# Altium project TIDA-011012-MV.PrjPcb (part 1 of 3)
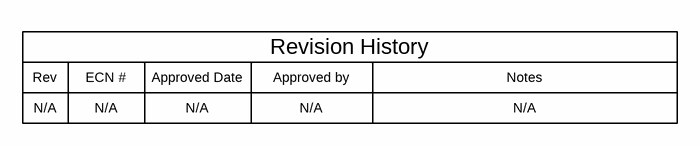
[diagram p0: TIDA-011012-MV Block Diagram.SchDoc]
CopyrightYear: 2026; EVM_orderable: NA; PCB_Rev: E1; PRJ_Customer: Public Release; PRJ_Engineer: A. Lechner/ R. Ruffo; PRJ_Number: TIDA-011012-MV; PRJ_Title: Change in menu Project|Project Options|Parameters; SCH_Rev: E1; TechSupport: http://www.ti.com/support; TID: TIDA-011012-MV
11 sheets, 567 parts. Net scope: hierarchical (ports join the sheet entries above them; power ports are global).
Board file: TIDA-011012-MV.PcbDoc
Sheets:
  TIDA-011012-MV Block Diagram.SchDoc
  TIDA-011012-MV Power Conversion.SchDoc
    U_TIDA-011012 Fans and Temp Sense = TIDA-011012-MV Fans and Temp Sense.SchDoc
    U_TIDA-011012 Optical Interface = TIDA-011012-MV Optical Interface.SchDoc
    U_TIDA-011012 Communication = TIDA-011012-MV Communication.SchDoc
    U_TIDA-011012 AC IV Sensing = TIDA-011012-MV AC IV Sensing.SchDoc
    U_TIDA-011012 DC IV Sensing = TIDA-011012-MV DC IV Sensing.SchDoc
    U_TIDA-011012 Current Comparator = TIDA-011012-MV Current Comparator.SchDoc
    U_TIDA-011012 Switch Node Hall Current Sensing = TIDA-011012-MV Switch Node Hall Current Sensing.SchDoc
    U_TIDA-011012 Auxiliary Power = TIDA-011012-MV Auxiliary Power.SchDoc
    U_TIDA-011012_Hardware = TIDA-011012-MV_Hardware.SchDoc

## Sheet TIDA-011012-MV Block Diagram.SchDoc
size 431 x 279 mm; Date: Not shown in title block; ApprovedBy: Not shown in title block; CheckedBy: Not shown in title block; Author: Not shown in title block; CompanyName: Not shown in title block; Engineer: Not shown in title block; Organization: Not shown in title block; Address1: Not shown in title block; Address2: Not shown in title block; Address3: Not shown in title block; Address4: Not shown in title block; DocumentNumber: 1; Revision: Use project parameter SCH_Rev; SheetNumber: 1; SheetTotal: 11; PageSetup: Record=PageOptions¦CenterHorizontal=True¦CenterVertical=True¦PrintScale=1.00¦XCorrection=1.00¦YCorrection=1.00¦PrintKind=0¦BorderSize=5000000¦LeftOffset=0¦BottomOffset=0¦Orientation=2¦PaperLength=1000¦PaperWidth=1000¦Scale=100¦PaperSource=15¦PrintQuality=600¦MediaType=1¦DitherType=10¦PaperKind=Letter¦PrintScaleMode=1

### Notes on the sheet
- Rev
- N/A
- ECN #
- Approved Date
- Approved by
- Revision History
- Notes

## Sheet TIDA-011012-MV Power Conversion.SchDoc
size 431 x 279 mm; Date: Not shown in title block; ApprovedBy: Not shown in title block; CheckedBy: Not shown in title block; Author: Not shown in title block; CompanyName: Not shown in title block; Engineer: Not shown in title block; Organization: Not shown in title block; Address1: Not shown in title block; Address2: Not shown in title block; Address3: Not shown in title block; Address4: Not shown in title block; DocumentNumber: 2; Revision: Use project parameter SCH_Rev; SheetNumber: 2; SheetTotal: 11; PageSetup: Record=PageOptions¦CenterHorizontal=True¦CenterVertical=True¦PrintScale=1.00¦XCorrection=1.00¦YCorrection=1.00¦PrintKind=0¦BorderSize=5000000¦LeftOffset=0¦BottomOffset=0¦Orientation=2¦PaperLength=1000¦PaperWidth=1000¦Scale=100¦PaperSource=15¦PrintQuality=600¦MediaType=1¦DitherType=10¦PaperKind=Letter¦PrintScaleMode=1
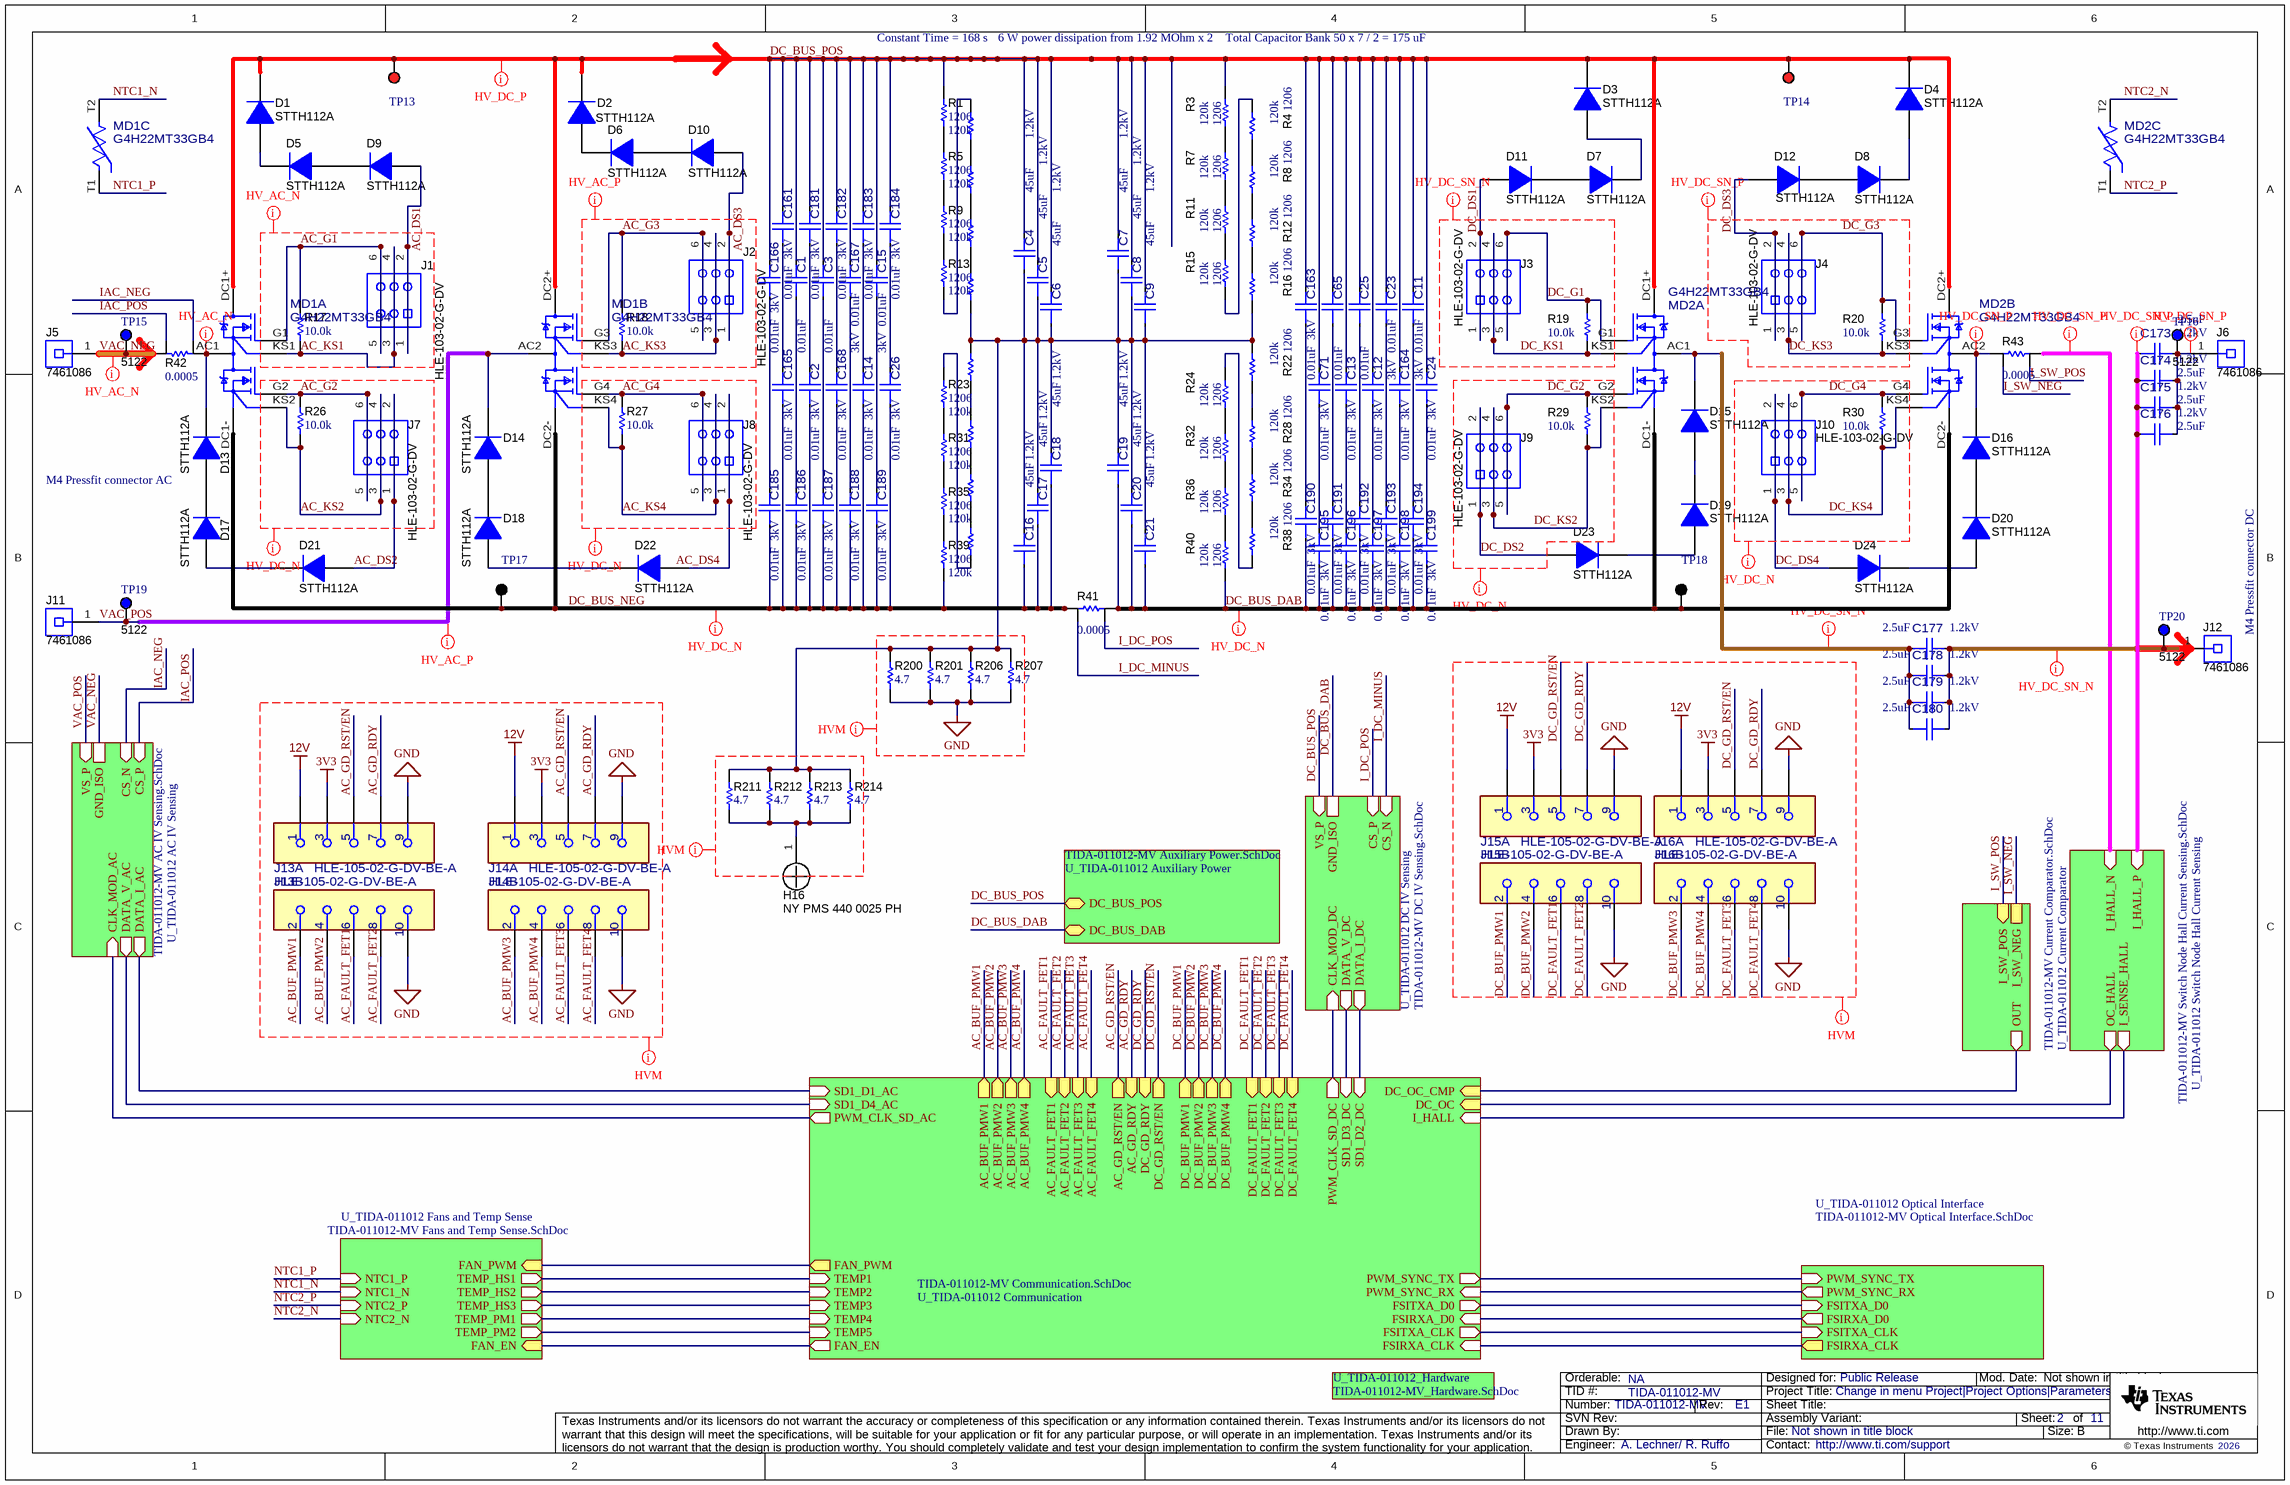
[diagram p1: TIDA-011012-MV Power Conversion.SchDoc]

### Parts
C1  ValueDisplayed: 0.01uF  [FP-C2220X103KHRAC7800_2220-MFG]  (hidden comment: C2220X103KHRAC7800)
C2  ValueDisplayed: 0.01uF  VDC_V: 3kV  [FP-C2220X103KHRAC7800_2220-MFG]  (hidden comment: C2220X103KHRAC7800)
C3  ValueDisplayed: 0.01uF  [FP-C2220X103KHRAC7800_2220-MFG]  (hidden comment: C2220X103KHRAC7800)
C4  ValueDisplayed: 45uF  VDC_V: 1.2kV  [FP-C4AQPEW5450M3BJ_RADIAL-MFG]  (hidden comment: C4AQPEW5450M3BJ)
C5  ValueDisplayed: 45uF  VDC_V: 1.2kV  [FP-C4AQPEW5450M3BJ_RADIAL-MFG]  (hidden comment: C4AQPEW5450M3BJ)
C6  ValueDisplayed: 45uF  VDC_V: 1.2kV  [FP-C4AQPEW5450M3BJ_RADIAL-MFG]  (hidden comment: C4AQPEW5450M3BJ)
C7  ValueDisplayed: 45uF  VDC_V: 1.2kV  [FP-C4AQPEW5450M3BJ_RADIAL-MFG]  (hidden comment: C4AQPEW5450M3BJ)
C8  ValueDisplayed: 45uF  VDC_V: 1.2kV  [FP-C4AQPEW5450M3BJ_RADIAL-MFG]  (hidden comment: C4AQPEW5450M3BJ)
C9  ValueDisplayed: 45uF  VDC_V: 1.2kV  [FP-C4AQPEW5450M3BJ_RADIAL-MFG]  (hidden comment: C4AQPEW5450M3BJ)
C11  ValueDisplayed: 0.01uF  VDC_V: 3kV  [FP-C2220X103KHRAC7800_2220-MFG]  (hidden comment: C2220X103KHRAC7800)
C12  ValueDisplayed: 0.01uF  VDC_V: 3kV  [FP-C2220X103KHRAC7800_2220-MFG]  (hidden comment: C2220X103KHRAC7800)
C13  ValueDisplayed: 0.01uF  VDC_V: 3kV  [FP-C2220X103KHRAC7800_2220-MFG]  (hidden comment: C2220X103KHRAC7800)
C14  ValueDisplayed: 0.01uF  VDC_V: 3kV  [FP-C2220X103KHRAC7800_2220-MFG]  (hidden comment: C2220X103KHRAC7800)
C15  ValueDisplayed: 0.01uF  VDC_V: 3kV  [FP-C2220X103KHRAC7800_2220-MFG]  (hidden comment: C2220X103KHRAC7800)
C16  ValueDisplayed: 45uF  VDC_V: 1.2kV  [FP-C4AQPEW5450M3BJ_RADIAL-MFG]  (hidden comment: C4AQPEW5450M3BJ)
C17  ValueDisplayed: 45uF  VDC_V: 1.2kV  [FP-C4AQPEW5450M3BJ_RADIAL-MFG]  (hidden comment: C4AQPEW5450M3BJ)
C18  ValueDisplayed: 45uF  VDC_V: 1.2kV  [FP-C4AQPEW5450M3BJ_RADIAL-MFG]  (hidden comment: C4AQPEW5450M3BJ)
C19  ValueDisplayed: 45uF  VDC_V: 1.2kV  [FP-C4AQPEW5450M3BJ_RADIAL-MFG]  (hidden comment: C4AQPEW5450M3BJ)
C20  ValueDisplayed: 45uF  VDC_V: 1.2kV  [FP-C4AQPEW5450M3BJ_RADIAL-MFG]  (hidden comment: C4AQPEW5450M3BJ)
C21  ValueDisplayed: 45uF  VDC_V: 1.2kV  [FP-C4AQPEW5450M3BJ_RADIAL-MFG]  (hidden comment: C4AQPEW5450M3BJ)
C23  ValueDisplayed: 0.01uF  VDC_V: 3kV  [FP-C2220X103KHRAC7800_2220-MFG]  (hidden comment: C2220X103KHRAC7800)
C24  ValueDisplayed: 0.01uF  VDC_V: 3kV  [FP-C2220X103KHRAC7800_2220-MFG]  (hidden comment: C2220X103KHRAC7800)
C25  ValueDisplayed: 0.01uF  [FP-C2220X103KHRAC7800_2220-MFG]  (hidden comment: C2220X103KHRAC7800)
C26  ValueDisplayed: 0.01uF  VDC_V: 3kV  [FP-C2220X103KHRAC7800_2220-MFG]  (hidden comment: C2220X103KHRAC7800)
C65  ValueDisplayed: 0.01uF  [FP-C2220X103KHRAC7800_2220-MFG]  (hidden comment: C2220X103KHRAC7800)
C71  ValueDisplayed: 0.01uF  VDC_V: 3kV  [FP-C2220X103KHRAC7800_2220-MFG]  (hidden comment: C2220X103KHRAC7800)
C161  ValueDisplayed: 0.01uF  VDC_V: 3kV  [FP-C2220X103KHRAC7800_2220-MFG]  (hidden comment: C2220X103KHRAC7800)
C163  ValueDisplayed: 0.01uF  VDC_V: 3kV  [FP-C2220X103KHRAC7800_2220-MFG]  (hidden comment: C2220X103KHRAC7800)
C164  ValueDisplayed: 0.01uF  VDC_V: 3kV  [FP-C2220X103KHRAC7800_2220-MFG]  (hidden comment: C2220X103KHRAC7800)
C165  ValueDisplayed: 0.01uF  VDC_V: 3kV  [FP-C2220X103KHRAC7800_2220-MFG]  (hidden comment: C2220X103KHRAC7800)
C166  ValueDisplayed: 0.01uF  VDC_V: 3kV  [FP-C2220X103KHRAC7800_2220-MFG]  (hidden comment: C2220X103KHRAC7800)
C167  ValueDisplayed: 0.01uF  VDC_V: 3kV  [FP-C2220X103KHRAC7800_2220-MFG]  (hidden comment: C2220X103KHRAC7800)
C168  ValueDisplayed: 0.01uF  VDC_V: 3kV  [FP-C2220X103KHRAC7800_2220-MFG]  (hidden comment: C2220X103KHRAC7800)
C173  ValueDisplayed: 2.5uF  VDC_V: 1.2kV  [FP-C4ASPBW4250A3MJ_RADIAL-MFG]  (hidden comment: C4ASPBW4250A3MJ)
C174  ValueDisplayed: 2.5uF  VDC_V: 1.2kV  [FP-C4ASPBW4250A3MJ_RADIAL-MFG]  (hidden comment: C4ASPBW4250A3MJ)
C175  ValueDisplayed: 2.5uF  VDC_V: 1.2kV  [FP-C4ASPBW4250A3MJ_RADIAL-MFG]  (hidden comment: C4ASPBW4250A3MJ)
C176  ValueDisplayed: 2.5uF  VDC_V: 1.2kV  [FP-C4ASPBW4250A3MJ_RADIAL-MFG]  (hidden comment: C4ASPBW4250A3MJ)
C177  ValueDisplayed: 2.5uF  VDC_V: 1.2kV  [FP-C4ASPBW4250A3MJ_RADIAL-MFG]  (hidden comment: C4ASPBW4250A3MJ)
C178  ValueDisplayed: 2.5uF  VDC_V: 1.2kV  [FP-C4ASPBW4250A3MJ_RADIAL-MFG]  (hidden comment: C4ASPBW4250A3MJ)
C179  ValueDisplayed: 2.5uF  VDC_V: 1.2kV  [FP-C4ASPBW4250A3MJ_RADIAL-MFG]  (hidden comment: C4ASPBW4250A3MJ)
C180  ValueDisplayed: 2.5uF  VDC_V: 1.2kV  [FP-C4ASPBW4250A3MJ_RADIAL-MFG]  (hidden comment: C4ASPBW4250A3MJ)
C181  ValueDisplayed: 0.01uF  VDC_V: 3kV  [FP-C2220X103KHRAC7800_2220-MFG]  (hidden comment: C2220X103KHRAC7800)
C182  ValueDisplayed: 0.01uF  VDC_V: 3kV  [FP-C2220X103KHRAC7800_2220-MFG]  (hidden comment: C2220X103KHRAC7800)
C183  ValueDisplayed: 0.01uF  VDC_V: 3kV  [FP-C2220X103KHRAC7800_2220-MFG]  (hidden comment: C2220X103KHRAC7800)
C184  ValueDisplayed: 0.01uF  VDC_V: 3kV  [FP-C2220X103KHRAC7800_2220-MFG]  (hidden comment: C2220X103KHRAC7800)
C185  ValueDisplayed: 0.01uF  VDC_V: 3kV  [FP-C2220X103KHRAC7800_2220-MFG]  (hidden comment: C2220X103KHRAC7800)
C186  ValueDisplayed: 0.01uF  VDC_V: 3kV  [FP-C2220X103KHRAC7800_2220-MFG]  (hidden comment: C2220X103KHRAC7800)
C187  ValueDisplayed: 0.01uF  VDC_V: 3kV  [FP-C2220X103KHRAC7800_2220-MFG]  (hidden comment: C2220X103KHRAC7800)
C188  ValueDisplayed: 0.01uF  VDC_V: 3kV  [FP-C2220X103KHRAC7800_2220-MFG]  (hidden comment: C2220X103KHRAC7800)
C189  ValueDisplayed: 0.01uF  VDC_V: 3kV  [FP-C2220X103KHRAC7800_2220-MFG]  (hidden comment: C2220X103KHRAC7800)
C190  ValueDisplayed: 0.01uF  VDC_V: 3kV  [FP-C2220X103KHRAC7800_2220-MFG]  (hidden comment: C2220X103KHRAC7800)
C191  ValueDisplayed: 0.01uF  VDC_V: 3kV  [FP-C2220X103KHRAC7800_2220-MFG]  (hidden comment: C2220X103KHRAC7800)
C192  ValueDisplayed: 0.01uF  VDC_V: 3kV  [FP-C2220X103KHRAC7800_2220-MFG]  (hidden comment: C2220X103KHRAC7800)
C193  ValueDisplayed: 0.01uF  VDC_V: 3kV  [FP-C2220X103KHRAC7800_2220-MFG]  (hidden comment: C2220X103KHRAC7800)
C194  ValueDisplayed: 0.01uF  VDC_V: 3kV  [FP-C2220X103KHRAC7800_2220-MFG]  (hidden comment: C2220X103KHRAC7800)
C195  ValueDisplayed: 0.01uF  VDC_V: 3kV  [FP-C2220X103KHRAC7800_2220-MFG]  (hidden comment: C2220X103KHRAC7800)
C196  ValueDisplayed: 0.01uF  VDC_V: 3kV  [FP-C2220X103KHRAC7800_2220-MFG]  (hidden comment: C2220X103KHRAC7800)
C197  ValueDisplayed: 0.01uF  VDC_V: 3kV  [FP-C2220X103KHRAC7800_2220-MFG]  (hidden comment: C2220X103KHRAC7800)
C198  ValueDisplayed: 0.01uF  VDC_V: 3kV  [FP-C2220X103KHRAC7800_2220-MFG]  (hidden comment: C2220X103KHRAC7800)
C199  ValueDisplayed: 0.01uF  VDC_V: 3kV  [FP-C2220X103KHRAC7800_2220-MFG]  (hidden comment: C2220X103KHRAC7800)
D1  STTH112A  [SMA]
D2  STTH112A  [SMA]
D3  STTH112A  [SMA]
D4  STTH112A  [SMA]
D5  STTH112A  [SMA]
D6  STTH112A  [SMA]
D7  STTH112A  [SMA]
D8  STTH112A  [SMA]
D9  STTH112A  [SMA]
D10  STTH112A  [SMA]
D11  STTH112A  [SMA]
D12  STTH112A  [SMA]
D13  STTH112A  [SMA]
D14  STTH112A  [SMA]
D15  STTH112A  [SMA]
D16  STTH112A  [SMA]
D17  STTH112A  [SMA]
D18  STTH112A  [SMA]
D19  STTH112A  [SMA]
D20  STTH112A  [SMA]
D21  STTH112A  [SMA]
D22  STTH112A  [SMA]
D23  STTH112A  [SMA]
D24  STTH112A  [SMA]
H16  NY PMS 440 0025 PH  [NY PMS 440 0025 PH]
J1  HLE-103-02-G-DV  [Samtec_HLE-103-02-x-DV]
J2  HLE-103-02-G-DV  [Samtec_HLE-103-02-x-DV]
J3  HLE-103-02-G-DV  [Samtec_HLE-103-02-x-DV]
J4  HLE-103-02-G-DV  [Samtec_HLE-103-02-x-DV]
J5  7461086  [Wurth_7461086]
J6  7461086  [Wurth_7461086]
J7  HLE-103-02-G-DV  [Samtec_HLE-103-02-x-DV]
J8  HLE-103-02-G-DV  [Samtec_HLE-103-02-x-DV]
J9  HLE-103-02-G-DV  [Samtec_HLE-103-02-x-DV]
J10  HLE-103-02-G-DV  [Samtec_HLE-103-02-x-DV]
J11  7461086  [Wurth_7461086]
J12  7461086  [Wurth_7461086]
J13  HLE-105-02-G-DV-BE-A  [FP-HLE-105-02-G-DV-BE-A_CONN_RCPT_10-MFG]  (parts A,B of 2)
J14  HLE-105-02-G-DV-BE-A  [FP-HLE-105-02-G-DV-BE-A_CONN_RCPT_10-MFG]  (parts A,B of 2)
J15  HLE-105-02-G-DV-BE-A  [FP-HLE-105-02-G-DV-BE-A_CONN_RCPT_10-MFG]  (parts A,B of 2)
J16  HLE-105-02-G-DV-BE-A  [FP-HLE-105-02-G-DV-BE-A_CONN_RCPT_10-MFG]  (parts A,B of 2)
MD1  G4H22MT33GB4  [FP-G4H22MT33GB4_SiCPAK-G+_MODIFIED-MFG]  (parts A,B,C of 3)
MD2  G4H22MT33GB4  [FP-G4H22MT33GB4_SiCPAK-G+_MODIFIED-MFG]  (parts A,B,C of 3)
R1  ValueDisplayed: 120k  [1206]  (hidden comment: RC1206FR-07120KL)
R2  RC1206FR-07120KL  [1206]  (value not drawn)
R3  ValueDisplayed: 120k  [1206]  (hidden comment: RC1206FR-07120KL)
R4  ValueDisplayed: 120k  [1206]  (hidden comment: RC1206FR-07120KL)
R5  ValueDisplayed: 120k  [1206]  (hidden comment: RC1206FR-07120KL)
R6  RC1206FR-07120KL  [1206]  (value not drawn)
R7  ValueDisplayed: 120k  [1206]  (hidden comment: RC1206FR-07120KL)
R8  ValueDisplayed: 120k  [1206]  (hidden comment: RC1206FR-07120KL)
R9  ValueDisplayed: 120k  [1206]  (hidden comment: RC1206FR-07120KL)
R10  RC1206FR-07120KL  [1206]  (value not drawn)
R11  ValueDisplayed: 120k  [1206]  (hidden comment: RC1206FR-07120KL)
R12  ValueDisplayed: 120k  [1206]  (hidden comment: RC1206FR-07120KL)
R13  ValueDisplayed: 120k  [1206]  (hidden comment: RC1206FR-07120KL)
R14  RC1206FR-07120KL  [1206]  (value not drawn)
R15  ValueDisplayed: 120k  [1206]  (hidden comment: RC1206FR-07120KL)
R16  ValueDisplayed: 120k  [1206]  (hidden comment: RC1206FR-07120KL)
R17  ValueDisplayed: 10.0k  [0603]  (hidden comment: ERJ-3EKF1002V)
R18  ValueDisplayed: 10.0k  [0603]  (hidden comment: ERJ-3EKF1002V)
R19  ValueDisplayed: 10.0k  [0603]  (hidden comment: ERJ-3EKF1002V)
R20  ValueDisplayed: 10.0k  [0603]  (hidden comment: ERJ-3EKF1002V)
R21  RC1206FR-07120KL  [1206]  (value not drawn)
R22  ValueDisplayed: 120k  [1206]  (hidden comment: RC1206FR-07120KL)
R23  ValueDisplayed: 120k  [1206]  (hidden comment: RC1206FR-07120KL)
R24  ValueDisplayed: 120k  [1206]  (hidden comment: RC1206FR-07120KL)
R25  RC1206FR-07120KL  [1206]  (value not drawn)
R26  ValueDisplayed: 10.0k  [0603]  (hidden comment: ERJ-3EKF1002V)
R27  ValueDisplayed: 10.0k  [0603]  (hidden comment: ERJ-3EKF1002V)
R28  ValueDisplayed: 120k  [1206]  (hidden comment: RC1206FR-07120KL)
R29  ValueDisplayed: 10.0k  [0603]  (hidden comment: ERJ-3EKF1002V)
R30  ValueDisplayed: 10.0k  [0603]  (hidden comment: ERJ-3EKF1002V)
R31  ValueDisplayed: 120k  [1206]  (hidden comment: RC1206FR-07120KL)
R32  ValueDisplayed: 120k  [1206]  (hidden comment: RC1206FR-07120KL)
R33  RC1206FR-07120KL  [1206]  (value not drawn)
R34  ValueDisplayed: 120k  [1206]  (hidden comment: RC1206FR-07120KL)
R35  ValueDisplayed: 120k  [1206]  (hidden comment: RC1206FR-07120KL)
R36  ValueDisplayed: 120k  [1206]  (hidden comment: RC1206FR-07120KL)
R37  RC1206FR-07120KL  [1206]  (value not drawn)
R38  ValueDisplayed: 120k  [1206]  (hidden comment: RC1206FR-07120KL)
R39  ValueDisplayed: 120k  [1206]  (hidden comment: RC1206FR-07120KL)
R40  ValueDisplayed: 120k  [1206]  (hidden comment: RC1206FR-07120KL)
R41  ValueDisplayed: 0.0005  [WSL4026_0p5milli]  (hidden comment: WSL4026L5000FEB)
R42  ValueDisplayed: 0.0005  [WSL4026_0p5milli]  (hidden comment: WSL4026L5000FEB)
R43  ValueDisplayed: 0.0005  [WSL4026_0p5milli]  (hidden comment: WSL4026L5000FEB)
R200  ValueDisplayed: 4.7  [1206]  (hidden comment: CRCW12064R70JNEA)
R201  ValueDisplayed: 4.7  [1206]  (hidden comment: CRCW12064R70JNEA)
R206  ValueDisplayed: 4.7  [1206]  (hidden comment: CRCW12064R70JNEA)
R207  ValueDisplayed: 4.7  [1206]  (hidden comment: CRCW12064R70JNEA)
R211  ValueDisplayed: 4.7  [1206]  (hidden comment: CRCW12064R70JNEA)
R212  ValueDisplayed: 4.7  [1206]  (hidden comment: CRCW12064R70JNEA)
R213  ValueDisplayed: 4.7  [1206]  (hidden comment: CRCW12064R70JNEA)
R214  ValueDisplayed: 4.7  [1206]  (hidden comment: CRCW12064R70JNEA)
TP13  5010  [Keystone5010]  (value not drawn)
TP14  5010  [Keystone5010]  (value not drawn)
TP15  5122  [Keystone5122]
TP16  5122  [Keystone5122]
TP17  5011  [Keystone5011]  (value not drawn)
TP18  5011  [Keystone5011]  (value not drawn)
TP19  5122  [Keystone5122]
TP20  5122  [Keystone5122]

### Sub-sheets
U_TIDA-011012 AC IV Sensing = TIDA-011012-MV AC IV Sensing.SchDoc: CS_P (in), CS_N (in), DATA_I_AC (out), GND_ISO, VS_P (in), DATA_V_AC (out), CLK_MOD_AC (in)
U_TIDA-011012 Auxiliary Power = TIDA-011012-MV Auxiliary Power.SchDoc: DC_BUS_POS (bidir), DC_BUS_DAB (bidir)
U_TIDA-011012 Communication = TIDA-011012-MV Communication.SchDoc: SD1_D1_AC (in), SD1_D2_DC (in), SD1_D3_DC (in), SD1_D4_AC (in), PWM_CLK_SD_AC (out), FAN_EN (out), TEMP1 (in), TEMP2 (in), TEMP3 (in), TEMP4 (in), TEMP5 (in), FSITXA_D0 (out), PWM_SYNC_TX (out), PWM_SYNC_RX (in), I_HALL (in), PWM_CLK_SD_DC (out), AC_FAULT_FET1 (in), AC_FAULT_FET2 (in), AC_GD_RST/EN (out), AC_BUF_PMW1 (out), AC_BUF_PMW2 (out), AC_BUF_PMW3 (out), AC_BUF_PMW4 (out), DC_GD_RDY (in), DC_FAULT_FET1 (in), DC_OC (in), DC_OC_CMP (in), DC_BUF_PMW1 (out), DC_BUF_PMW2 (out), DC_BUF_PMW3 (out), DC_BUF_PMW4 (out), AC_FAULT_FET3 (in), AC_FAULT_FET4 (in), DC_FAULT_FET2 (in), DC_FAULT_FET3 (in), DC_FAULT_FET4 (in), DC_GD_RST/EN (out), AC_GD_RDY (in), FAN_PWM (out), FSIRXA_D0 (in), FSITXA_CLK (out), FSIRXA_CLK (in)
U_TIDA-011012 Current Comparator = TIDA-011012-MV Current Comparator.SchDoc: OUT (out), I_SW_NEG, I_SW_POS (in)
U_TIDA-011012 DC IV Sensing = TIDA-011012-MV DC IV Sensing.SchDoc: CS_P (in), CS_N (in), DATA_I_DC (out), GND_ISO, VS_P (in), DATA_V_DC (out), CLK_MOD_DC (in)
U_TIDA-011012 Fans and Temp Sense = TIDA-011012-MV Fans and Temp Sense.SchDoc: TEMP_HS1 (out), TEMP_HS2 (out), TEMP_HS3 (out), TEMP_PM2 (out), NTC1_P (in), NTC1_N (in), NTC2_P (in), NTC2_N (in), TEMP_PM1 (out), FAN_EN (in), FAN_PWM (in)
U_TIDA-011012 Optical Interface = TIDA-011012-MV Optical Interface.SchDoc: PWM_SYNC_RX (out), FSITXA_D0 (in), PWM_SYNC_TX (in), FSITXA_CLK (in), FSIRXA_D0 (out), FSIRXA_CLK (out)
U_TIDA-011012 Switch Node Hall Current Sensing = TIDA-011012-MV Switch Node Hall Current Sensing.SchDoc: I_HALL_P (in), I_HALL_N (in), I_SENSE_HALL (out), OC_HALL (out)
U_TIDA-011012_Hardware = TIDA-011012-MV_Hardware.SchDoc: no entries

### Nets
3V3: J13.3 J14.3 J15.3 J16.3
12V: J13.1 J14.1 J15.1 J16.1
GND: J13.9 J13.10 J14.9 J14.10 J15.9 J15.10 J16.9 J16.10 R200.1 R201.1 R206.1 R207.1
AC_BUF_PMW1: J13.2 ; sheet U_TIDA-011012 Communication/AC_BUF_PMW1
AC_BUF_PMW2: J13.4 ; sheet U_TIDA-011012 Communication/AC_BUF_PMW2
AC_BUF_PMW3: J14.2 ; sheet U_TIDA-011012 Communication/AC_BUF_PMW3
AC_BUF_PMW4: J14.4 ; sheet U_TIDA-011012 Communication/AC_BUF_PMW4
AC_DS1: D9.2(A) J1.1 J1.2
AC_DS2: D21.2(A) J7.1 J7.2
AC_DS3: D10.2(A) J2.1 J2.2
AC_FAULT_FET1: J13.6 ; sheet U_TIDA-011012 Communication/AC_FAULT_FET1
AC_FAULT_FET2: J13.8 ; sheet U_TIDA-011012 Communication/AC_FAULT_FET2
AC_FAULT_FET3: J14.6 ; sheet U_TIDA-011012 Communication/AC_FAULT_FET3
AC_FAULT_FET4: J14.8 ; sheet U_TIDA-011012 Communication/AC_FAULT_FET4
AC_G1: J1.5 J1.6 MD1.G1 R17.1
AC_G2: J7.5 J7.6 MD1.G2 R26.1
AC_G3: J2.5 J2.6 MD1.G3 R18.1
AC_G4: J8.5 J8.6 MD1.G4 R27.1
AC_GD_RDY: J13.7 J14.7 ; sheet U_TIDA-011012 Communication/AC_GD_RDY
AC_GD_RST/EN: J13.5 J14.5 ; sheet U_TIDA-011012 Communication/AC_GD_RST/EN
AC_KS1: J1.3 J1.4 MD1.KS1 R17.2
AC_KS2: J7.3 J7.4 MD1.KS2 R26.2
AC_KS3: J2.3 J2.4 MD1.KS3 R18.2
AC_KS4: J8.3 J8.4 MD1.KS4 R27.2
CLK_MOD_AC: sheet U_TIDA-011012 Communication/PWM_CLK_SD_AC, sheet U_TIDA-011012 AC IV Sensing/CLK_MOD_AC
CLK_MOD_DC: sheet U_TIDA-011012 Communication/PWM_CLK_SD_DC, sheet U_TIDA-011012 DC IV Sensing/CLK_MOD_DC
DATA_I_AC: sheet U_TIDA-011012 Communication/SD1_D1_AC, sheet U_TIDA-011012 AC IV Sensing/DATA_I_AC
DATA_I_DC: sheet U_TIDA-011012 Communication/SD1_D2_DC, sheet U_TIDA-011012 DC IV Sensing/DATA_I_DC
DATA_V_AC: sheet U_TIDA-011012 Communication/SD1_D4_AC, sheet U_TIDA-011012 AC IV Sensing/DATA_V_AC
DATA_V_DC: sheet U_TIDA-011012 Communication/SD1_D3_DC, sheet U_TIDA-011012 DC IV Sensing/DATA_V_DC
DC_BUF_PMW1: J15.2 ; sheet U_TIDA-011012 Communication/DC_BUF_PMW1
DC_BUF_PMW2: J15.4 ; sheet U_TIDA-011012 Communication/DC_BUF_PMW2
DC_BUF_PMW3: J16.2 ; sheet U_TIDA-011012 Communication/DC_BUF_PMW3
DC_BUF_PMW4: J16.4 ; sheet U_TIDA-011012 Communication/DC_BUF_PMW4
DC_BUS_DAB: C19.1 C20.1 C21.1 C190.1 C191.1 C192.1 C193.1 C194.1 C195.1 C196.1 C197.1 C198.1 C199.1 MD2.DC1- MD2.DC2- R40.1 R41.1 TP18.1 ; sheet U_TIDA-011012 DC IV Sensing/GND_ISO, sheet U_TIDA-011012 Auxiliary Power/DC_BUS_DAB
DC_BUS_NEG: C2.1 C14.1 C16.1 C17.1 C18.1 C26.1 C165.1 C168.1 C185.1 C186.1 C187.1 C188.1 C189.1 MD1.DC1- MD1.DC2- R39.1 R41.2 TP17.1
DC_BUS_POS: C1.2 C3.2 C4.2 C5.2 C6.2 C7.2 C8.2 C9.2 C11.2 C12.2 C13.2 C15.2 C23.2 C24.2 C25.2 C65.2 C71.2 C161.2 C163.2 C164.2 C166.2 C167.2 C181.2 C182.2 C183.2 C184.2 D1.1(K) D2.1(K) D3.1(K) D4.1(K) MD1.DC1+ MD1.DC2+ MD2.DC1+ MD2.DC2+ R1.2 R3.2 TP13.1 TP14.1 ; sheet U_TIDA-011012 DC IV Sensing/VS_P, sheet U_TIDA-011012 Auxiliary Power/DC_BUS_POS
DC_DS1: D11.2(A) J3.1 J3.2
DC_DS2: D23.2(A) J9.1 J9.2
DC_DS3: D12.2(A) J4.1 J4.2
DC_DS4: D24.2(A) J10.1 J10.2
DC_FAULT_FET1: J15.6 ; sheet U_TIDA-011012 Communication/DC_FAULT_FET1
DC_FAULT_FET2: J15.8 ; sheet U_TIDA-011012 Communication/DC_FAULT_FET2
DC_FAULT_FET3: J16.6 ; sheet U_TIDA-011012 Communication/DC_FAULT_FET3
DC_FAULT_FET4: J16.8 ; sheet U_TIDA-011012 Communication/DC_FAULT_FET4
DC_G1: J3.5 J3.6 MD2.G1 R19.2
DC_G2: J9.5 J9.6 MD2.G2 R29.2
DC_G3: J4.5 J4.6 MD2.G3 R20.2
DC_G4: J10.5 J10.6 MD2.G4 R30.2
DC_GD_RDY: J15.7 J16.7 ; sheet U_TIDA-011012 Communication/DC_GD_RDY
DC_GD_RST/EN: J15.5 J16.5 ; sheet U_TIDA-011012 Communication/DC_GD_RST/EN
DC_KS1: J3.3 J3.4 MD2.KS1 R19.1
DC_KS2: J9.3 J9.4 MD2.KS2 R29.1
DC_KS3: J4.3 J4.4 MD2.KS3 R20.1
DC_KS4: J10.3 J10.4 MD2.KS4 R30.1
DC_OC: sheet U_TIDA-011012 Communication/DC_OC, sheet U_TIDA-011012 Switch Node Hall Current Sensing/OC_HALL
DC_OC_CMP: sheet U_TIDA-011012 Communication/DC_OC_CMP, sheet U_TIDA-011012 Current Comparator/OUT
FAN_EN: sheet U_TIDA-011012 Fans and Temp Sense/FAN_EN, sheet U_TIDA-011012 Communication/FAN_EN
FAN_PWM: sheet U_TIDA-011012 Fans and Temp Sense/FAN_PWM, sheet U_TIDA-011012 Communication/FAN_PWM
FSIRXA_CLK: sheet U_TIDA-011012 Optical Interface/FSIRXA_CLK, sheet U_TIDA-011012 Communication/FSIRXA_CLK
FSIRXA_D0: sheet U_TIDA-011012 Optical Interface/FSIRXA_D0, sheet U_TIDA-011012 Communication/FSIRXA_D0
FSITXA_CLK: sheet U_TIDA-011012 Optical Interface/FSITXA_CLK, sheet U_TIDA-011012 Communication/FSITXA_CLK
FSITXA_D0: sheet U_TIDA-011012 Optical Interface/FSITXA_D0, sheet U_TIDA-011012 Communication/FSITXA_D0
I_DC_MINUS: R41.4 ; sheet U_TIDA-011012 DC IV Sensing/CS_N
I_DC_POS: R41.3 ; sheet U_TIDA-011012 DC IV Sensing/CS_P
I_HALL: sheet U_TIDA-011012 Communication/I_HALL, sheet U_TIDA-011012 Switch Node Hall Current Sensing/I_SENSE_HALL
I_HALL_N: R43.1 ; sheet U_TIDA-011012 Switch Node Hall Current Sensing/I_HALL_N
I_HALL_P: C173.1 C174.1 C175.1 C176.1 ; sheet U_TIDA-011012 Switch Node Hall Current Sensing/I_HALL_P
I_SW_NEG: R43.4 ; sheet U_TIDA-011012 Current Comparator/I_SW_NEG
I_SW_POS: R43.3 ; sheet U_TIDA-011012 Current Comparator/I_SW_POS
IAC_NEG: R42.3 ; sheet U_TIDA-011012 AC IV Sensing/CS_N
IAC_POS: R42.4 ; sheet U_TIDA-011012 AC IV Sensing/CS_P
NTC1_N: MD1.T2 ; sheet U_TIDA-011012 Fans and Temp Sense/NTC1_N
NTC1_P: MD1.T1 ; sheet U_TIDA-011012 Fans and Temp Sense/NTC1_P
NTC2_N: MD2.T2 ; sheet U_TIDA-011012 Fans and Temp Sense/NTC2_N
NTC2_P: MD2.T1 ; sheet U_TIDA-011012 Fans and Temp Sense/NTC2_P
PWM_SYNC_RX: sheet U_TIDA-011012 Optical Interface/PWM_SYNC_RX, sheet U_TIDA-011012 Communication/PWM_SYNC_RX
PWM_SYNC_TX: sheet U_TIDA-011012 Optical Interface/PWM_SYNC_TX, sheet U_TIDA-011012 Communication/PWM_SYNC_TX
TEMP1: sheet U_TIDA-011012 Fans and Temp Sense/TEMP_HS1, sheet U_TIDA-011012 Communication/TEMP1
TEMP2: sheet U_TIDA-011012 Fans and Temp Sense/TEMP_HS2, sheet U_TIDA-011012 Communication/TEMP2
TEMP3: sheet U_TIDA-011012 Fans and Temp Sense/TEMP_HS3, sheet U_TIDA-011012 Communication/TEMP3
TEMP4: sheet U_TIDA-011012 Fans and Temp Sense/TEMP_PM1, sheet U_TIDA-011012 Communication/TEMP4
TEMP5: sheet U_TIDA-011012 Fans and Temp Sense/TEMP_PM2, sheet U_TIDA-011012 Communication/TEMP5
VAC_NEG: J5.1 R42.2 TP15.1 ; sheet U_TIDA-011012 AC IV Sensing/GND_ISO  [project net GND_ISO_AC_SENS]
VAC_POS: D14.1(K) J11.1 MD1.AC2 TP19.1 ; sheet U_TIDA-011012 AC IV Sensing/VS_P
NetC1_1: C1.1 C186.2
NetC2_2: C2.2 C181.1
NetC3_1: C3.1 C187.2
NetC4_1: C4.1 C5.1 C6.1 C7.1 C8.1 C9.1 C16.2 C17.2 C18.2 C19.2 C20.2 C21.2 R14.2 R16.2 R21.1 R22.1 R200.2 R201.2 R206.2 R207.2 R211.2 R212.2 R213.2 R214.2
NetC11_1: C11.1 C194.2
NetC12_1: C12.1 C197.2
NetC13_1: C13.1 C196.2
NetC14_2: C14.2 C183.1
NetC15_1: C15.1 C189.2
NetC23_1: C23.1 C193.2
NetC24_1: C24.1 C199.2
NetC25_1: C25.1 C192.2
NetC26_2: C26.2 C184.1
NetC65_1: C65.1 C191.2
NetC71_1: C71.1 C195.2
NetC161_1: C161.1 C165.2
NetC163_1: C163.1 C190.2
NetC164_1: C164.1 C198.2
NetC166_1: C166.1 C185.2
NetC167_1: C167.1 C188.2
NetC168_2: C168.2 C182.1
NetC173_2: C173.2 C174.2 C175.2 C176.2 J6.1 TP16.1
NetC177_1: C177.1 C178.1 C179.1 C180.1 D15.1(K) MD2.AC1
NetC177_2: C177.2 C178.2 C179.2 C180.2 J12.1 TP20.1
NetD1_2: D1.2(A) D5.1(K)
NetD2_2: D2.2(A) D6.1(K)
NetD3_2: D3.2(A) D7.1(K)
NetD4_2: D4.2(A) D8.1(K)
NetD5_2: D5.2(A) D9.1(K)
NetD6_2: D6.2(A) D10.1(K)
NetD7_2: D7.2(A) D11.1(K)
NetD8_2: D8.2(A) D12.1(K)
NetD13_1: D13.1(K) MD1.AC1 R42.1
NetD13_2: D13.2(A) D17.1(K)
NetD14_2: D14.2(A) D18.1(K)
NetD15_2: D15.2(A) D19.1(K)
NetD16_1: D16.1(K) MD2.AC2 R43.2
NetD16_2: D16.2(A) D20.1(K)
NetD17_2: D17.2(A) D21.1(K)
NetD18_2: D18.2(A) D22.1(K)
NetD19_2: D19.2(A) D23.1(K)
NetD20_2: D20.2(A) D24.1(K)
NetD22_2: D22.2(A) J8.1 J8.2
NetH16_1: H16.1 R211.1 R212.1 R213.1 R214.1
NetR1_1: R1.1 R5.2
NetR2_1: R2.1 R13.1
NetR2_2: R2.2 R6.1
NetR3_1: R3.1 R7.2
NetR4_1: R4.1 R15.1
NetR4_2: R4.2 R8.1
NetR5_1: R5.1 R9.2
NetR6_2: R6.2 R10.1
NetR7_1: R7.1 R11.2
NetR8_2: R8.2 R12.1
NetR9_1: R9.1 R13.2
NetR10_2: R10.2 R14.1
NetR11_1: R11.1 R15.2
NetR12_2: R12.2 R16.1
NetR21_2: R21.2 R25.1
NetR22_2: R22.2 R28.1
NetR23_1: R23.1 R31.2
NetR23_2: R23.2 R37.2
NetR24_1: R24.1 R32.2
NetR24_2: R24.2 R38.2
NetR25_2: R25.2 R33.1
NetR28_2: R28.2 R34.1
NetR31_1: R31.1 R35.2
NetR32_1: R32.1 R36.2
NetR33_2: R33.2 R37.1
NetR34_2: R34.2 R38.1
NetR35_1: R35.1 R39.2
NetR36_1: R36.1 R40.2

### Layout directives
net class HV_AC_P: AC_G3, AC_KS3, VAC_POS
net class HV_AC_N: AC_G1, AC_KS1, GND_ISO_AC_SENS, NetD13_1
net class HV_DC_N: AC_G2, AC_G4, AC_KS2, AC_KS4, DC_BUS_DAB, DC_BUS_NEG, DC_DS2, DC_G2, DC_G4, DC_KS2, DC_KS4
net class HV_DC_P: DC_BUS_POS
net class HV_DC_SN_N: DC_DS1, DC_G1, DC_KS1, NetC177_1, NetC177_2
net class HV_DC_SN_P: DC_DS3, DC_G3, DC_KS3, I_HALL_N, I_HALL_P, NetC173_2, NetD16_1
net class HVM: 3V3, 12V, (no net found under the mark), AC_BUF_PMW1, AC_BUF_PMW2, AC_BUF_PMW3, AC_BUF_PMW4, AC_FAULT_FET1, AC_FAULT_FET2, AC_FAULT_FET3, AC_FAULT_FET4, AC_GD_RDY, AC_GD_RST/EN, DC_BUF_PMW1, DC_BUF_PMW2, DC_BUF_PMW3, DC_BUF_PMW4, DC_FAULT_FET1, DC_FAULT_FET2, DC_FAULT_FET3, DC_FAULT_FET4, DC_GD_RDY, DC_GD_RST/EN, GND

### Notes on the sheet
- Constant Time = 168 s
- 6 W power dissipation from 1.92 MOhm x 2
- Total Capacitor Bank 50 x 7 / 2 = 175 uF
- M4 Pressfit connector AC
- (near J12) M4 Pressfit connector DC
- Labels drawn without touching a wire or pin: AC_DS4

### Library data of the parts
C1-C3 C11-C15 C23-C26 C65 C71 C161 C163-C168 C181-C199 = CMP-0128868-1: 10000 pF ±10% 3000V (3kV) Ceramic Capacitor X7R 2220 (5750 Metric); Manufacturer: KEMET; AEC Grade: NA; AEC Qualified: No; Cap_F: 10nF; SizeZ_mm: 2.2mm; TempCo: 15%; Value: 10nF
C4-C9 C16-C21 = CMP-0128781-1: 45 µF Film Capacitor 1200V (1.2kV) Polypropylene (PP), Metallized Radial - 4 Leads; Manufacturer: KEMET; AEC Grade: Grade 2; AEC Qualified: Yes; Cap_F: 45µF; SizeZ_mm: 65.3mm; Tolerance_%: 5%; Value: 45µF
C173-C180 = CMP-0128874-1: 2.5 µF Film Capacitor 630V 1200V (1.2kV) Polypropylene (PP), Metallized Radial - 4 Leads; Manufacturer: KEMET; AEC Qualified: No; Cap_F: 2.5µF; SizeZ_mm: 45mm; Tolerance_%: 5%; Value: 2.5µF
D1-D24 = CMP-0077081-2: Diode, Ultrafast, 1200 V, 1 A, SMA; Manufacturer: STMicroelectronics; AEC Qualified: N; TJmax_C: 175°C; SizeX_mm: 5.59; Green_Lifecycle: Not Set; Io_A: 1A; Value2: 1.9V; SizeY_mm: 2.92; SizeZ_mm: 2.87; AEC Category: Q101; Value: 1200V; SizeAreaWB_mm2: 37.3428; Vr_V: 1.2kV; Green_REACh: Incomplete; SizeArea_mm2: 16.3228
H16 = CMP-0003617-1: Machine Screw, Round, #4-40 x 1/4, Nylon, Philips panhead; Manufacturer: B&F Fastener Supply; CompType: Hardware
J1-J4 J7-J10 = CMP-0082272-1: Receptacle, 2.54mm, 3x2, Gold, SMT; Manufacturer: Samtec; Pitch_mm: 2.54; Gender: Female; Cert_UL: Y; Voltage_V: 400V; Current_A: 4.1A; Row_Count: 2; CompType: Socket Strip
J5 J6 J11 J12 = CMP-0054757-1: Power Element Bush, M4, 12, TH; Manufacturer: Wurth Elektronik; CNHeader: FALSE; Gender: Female; CompType: Screw Terminal; Pitch_mm: 2.54
J13-J16 = CMP-0127514-1: Conn Socket Strip SKT 10 POS 2.54mm Solder ST Top Entry SMD Tube; Manufacturer: Samtec; ContactFinish: Gold,Nickel; Current_A: 4.1A; Row_Count: 2; Voltage_V: 566V; AEC Grade: NA; AEC Qualified: No; Conn Gender: Female; Conn Orientation: Vertical; Is Female: yes; SizeZ_mm: 3.79mm
MD1 MD2 = CMP-0128745-2: 3300V 22.5mΩ Full-Bridge / Dual-Half-Bridge SiC Module; Manufacturer: Navitas Semiconductor; AEC Qualified: No; IdsMax_A: 105A; QgTyp_nC: 590nC @ 18V; Rdson45_ohm: 22.5m; SizeZ_mm: 12.9mm; VdsMax_V: 3.3kV; Vgs_V: 18V; Input Capacitance At Vds: 13820pF @ 2000V; Threshold Vgs Max: 4.3V; Threshold Vgs Min: 2.5V; TJmax_C: +175°C; Typ Forward Diode Voltage: 4V; ChMode: Enhancement
R1 R3-R5 R7-R9 R11-R13 R15 R16 R22-R24 R28 R31 R32 R34-R36 R38-R40 = CMP-0017868-2: RES, 120 k, 1%, 0.25 W, 1206; Manufacturer: Yageo America; Power_W: 250mW; TempCo: 100 ppm/C; U/M: EA; Value: 120k; SizeX_mm: 3.2; SizeY_mm: 1.6; SizeZ_mm: 1.35; Value2: 0.25W; SizeArea_mm2: 5.12; VDC_V: 200V; AEC Category: Q200
R2 R6 R10 R14 R21 R25 R33 R37 = CMP-0017868-2: RES, 120 k, 1%, 0.25 W, 1206; Manufacturer: Yageo America; Power_W: 250mW; TempCo: 100 ppm/C; Value_Code: 120k; U/M: EA; Value: 120k; SizeX_mm: 3.2; SizeY_mm: 1.6; SizeZ_mm: 1.35; Value2: 0.25W; SizeArea_mm2: 5.12; VDC_V: 200V; AEC Category: Q200
R17-R20 R26 R27 R29 R30 = CMP-0022684-3: RES, 10.0 k, 1%, 0.1 W, 0603; Manufacturer: Panasonic; Power_W: 100mW; TempCo: 100 ppm/C; Value_Code: 10k0; U/M: EA; Value: 10.0k; EIA_Code: E96; Res_ohm: 10k; SizeX_mm: 1.6; SizeY_mm: 0.8; SizeZ_mm: 1; Value2: 0.1W; SizeArea_mm2: 1.28; VDC_V: 75V; AEC Category: Q200
R41-R43 = CMP-0065757-2: RES, 0.0005, 1%, 3 W, 4026; Manufacturer: Vishay-Dale; Power_W: 3W; TempCo: 75 ppm/C; Value_Code: L5000; U/M: EA; Value: 0.0005; Res_ohm: 500µ; CompType: Resistor; AEC Qualified: N; AEC Category: Q200
R200 R201 R206 R207 R211-R214 = CMP-0018693-3: RES, 4.7, 5%, 0.25 W, AEC-Q200 Grade 0, 1206; Manufacturer: Vishay-Dale; Power_W: 250mW; TempCo: 200 ppm/C; Value_Code: 4R70; Value: 4.7; EIA_Code: E24; SizeX_mm: 3.2; SizeY_mm: 1.6; SizeZ_mm: 1.35; Value2: 0.25W; SizeArea_mm2: 5.12; AEC Qualified: Y; VDC_V: 200V; AEC Category: Q200; AEC Grade: 0
TP13 TP14 = CMP-0055147-2: Test Point, Multipurpose, Red, TH; Manufacturer: Keystone Electronics; CT: TRUE; ContactFinish: Silver; Green_Lifecycle: Active; CNHeader: FALSE; Green_REACh: Passed
TP15 TP16 TP19 TP20 = CMP-0055155-2: Test Point, Compact, Blue, TH; Manufacturer: Keystone Electronics; Green_Lifecycle: Active; CNHeader: FALSE; ContactFinish: Silver; CT: TRUE; Green_REACh: Passed
TP17 TP18 = CMP-0055148-2: Test Point, Multipurpose, Black, TH; Manufacturer: Keystone Electronics; CNHeader: FALSE; ContactFinish: Silver; Green_REACh: Passed; Green_Lifecycle: Active; CT: TRUE

## Sheet TIDA-011012-MV Fans and Temp Sense.SchDoc
size 431 x 279 mm; Date: Not shown in title block; ApprovedBy: Not shown in title block; CheckedBy: Not shown in title block; Author: Not shown in title block; CompanyName: Not shown in title block; Engineer: Not shown in title block; Organization: Not shown in title block; Address1: Not shown in title block; Address2: Not shown in title block; Address3: Not shown in title block; Address4: Not shown in title block; DocumentNumber: 9; Revision: Use project parameter SCH_Rev; SheetNumber: 9; SheetTotal: 11; PageSetup: Record=PageOptions¦CenterHorizontal=True¦CenterVertical=True¦PrintScale=1.00¦XCorrection=1.00¦YCorrection=1.00¦PrintKind=0¦BorderSize=5000000¦LeftOffset=0¦BottomOffset=0¦Orientation=2¦PaperLength=1000¦PaperWidth=1000¦Scale=100¦PaperSource=15¦PrintQuality=600¦MediaType=1¦DitherType=10¦PaperKind=Letter¦PrintScaleMode=1
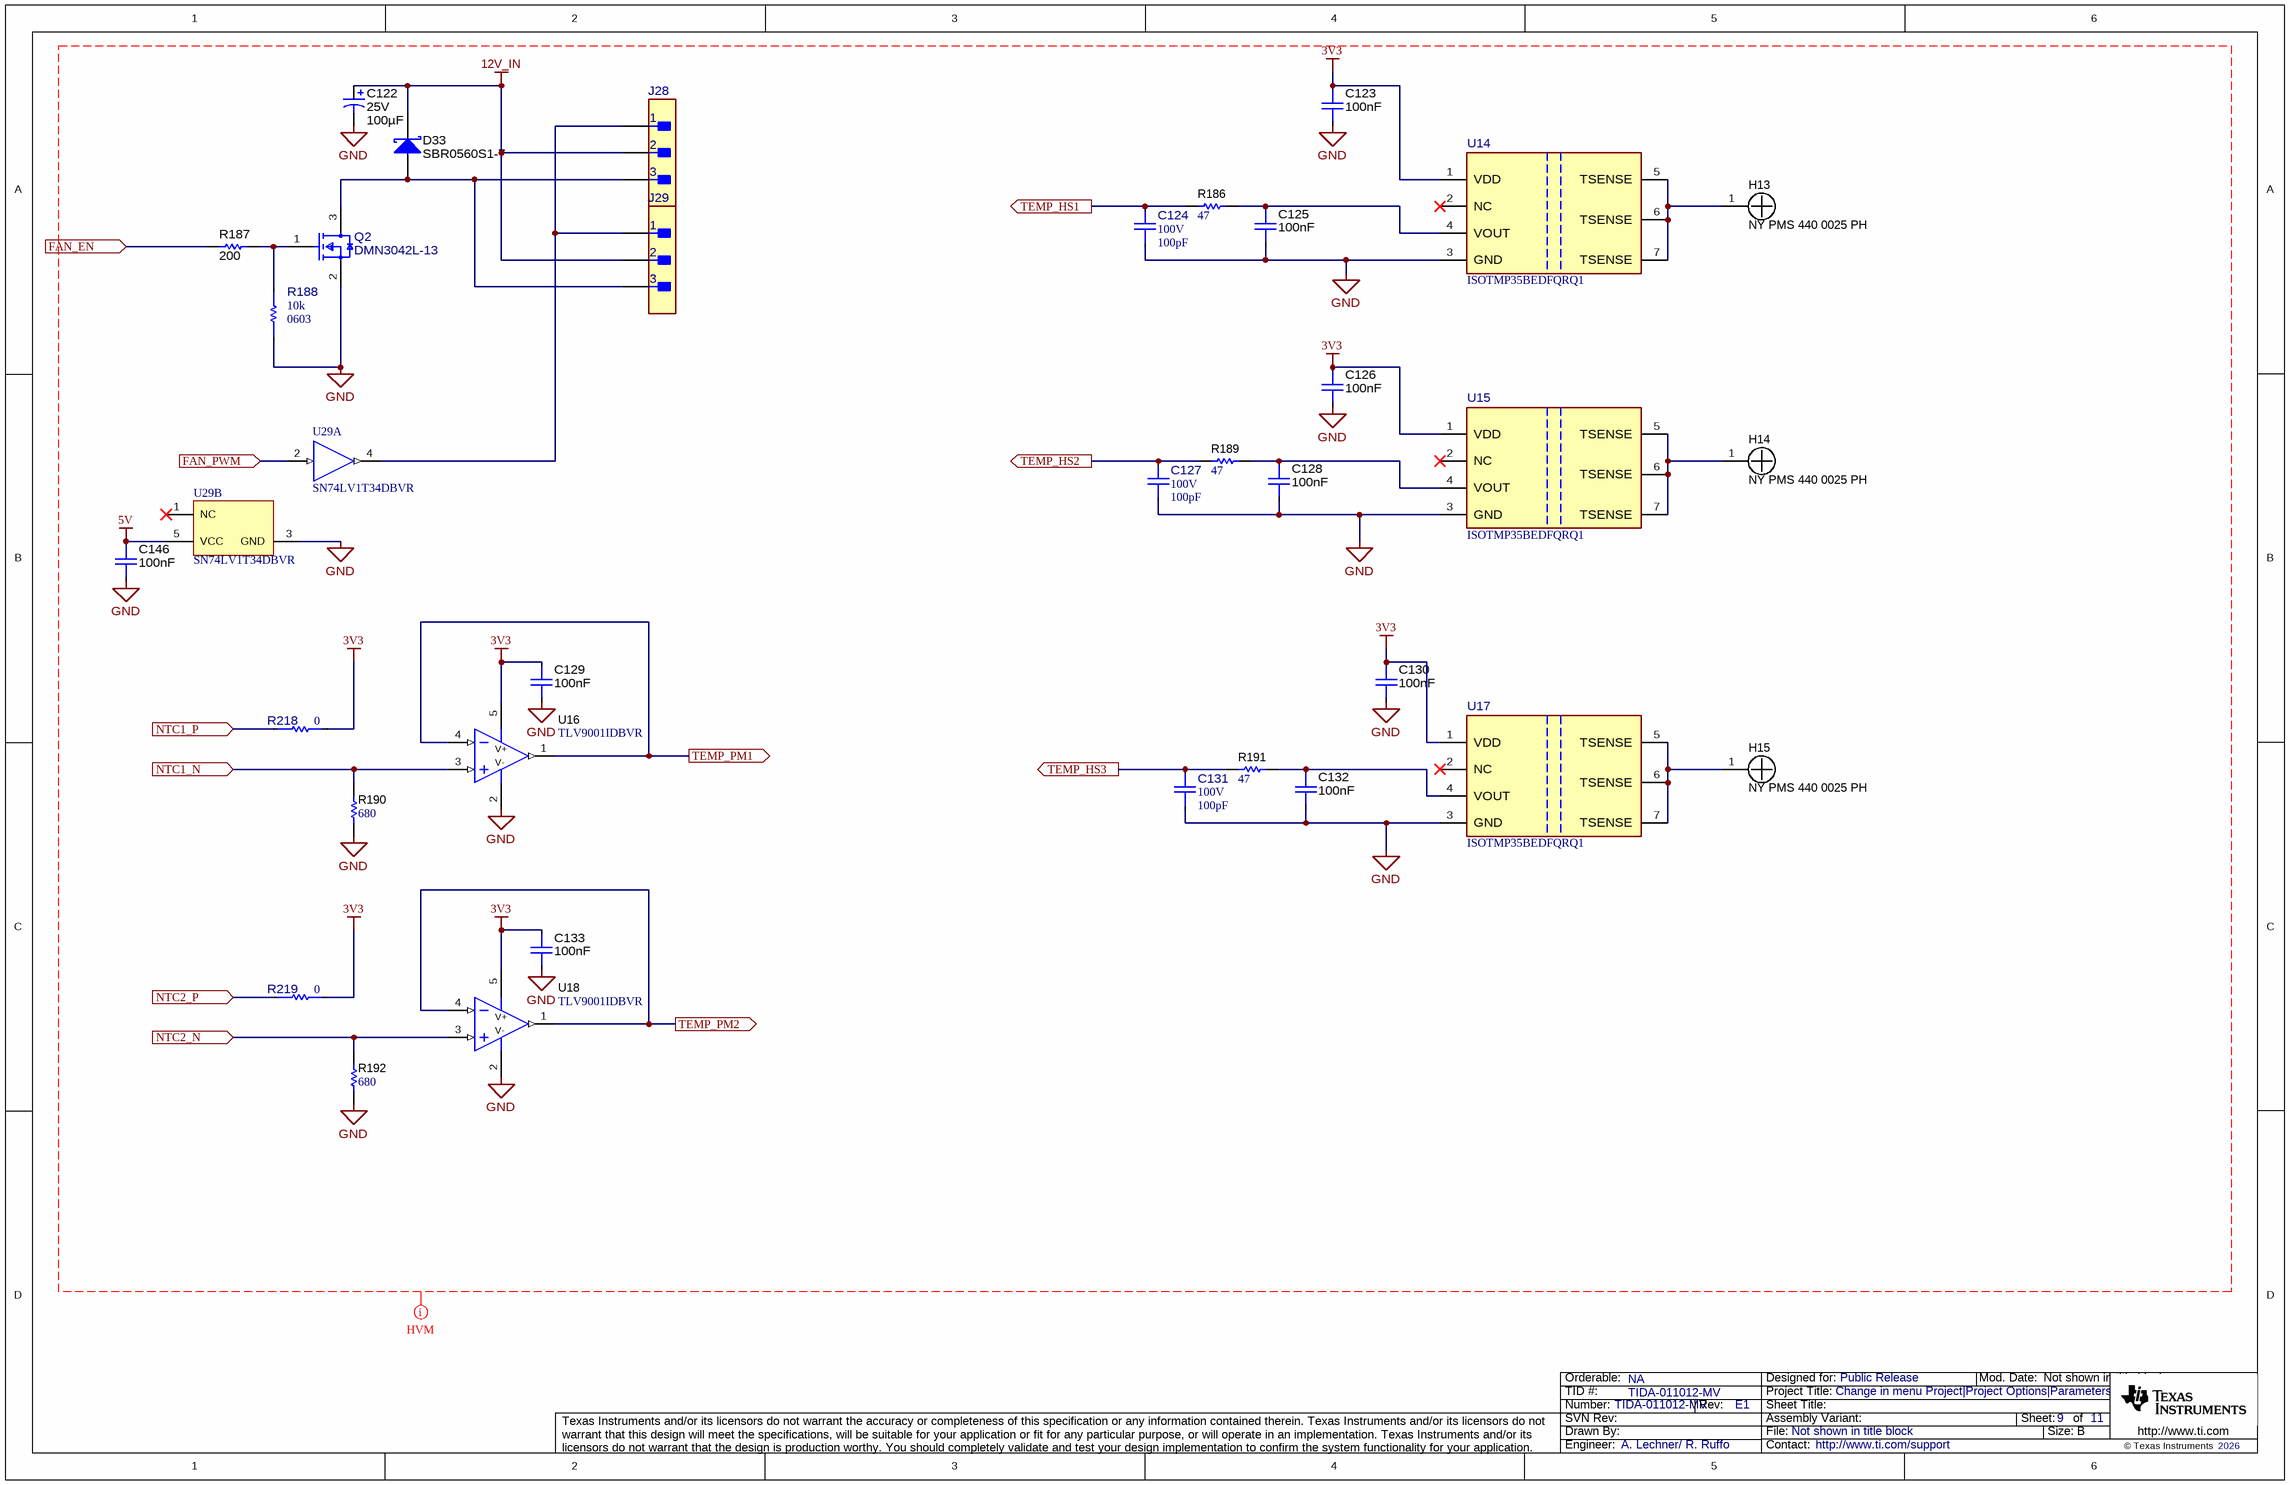
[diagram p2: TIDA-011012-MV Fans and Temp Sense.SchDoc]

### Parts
C122  VDC_V: 25V  ValueDisplayed: 100µF  [UWT_630x770]  (hidden comment: UWT1E101MCL1GS)
C123  Cap_F: 100nF  [FP-CL10B104KA8VPJC_0603-MFG]  (hidden comment: CL10B104KA8VPJC)
C124  VDC_V: 100V  Cap_F: 100pF  [FP-06031C101JAT2A_0603-MFG]  (hidden comment: 06031C101JAT2A)
C125  Cap_F: 100nF  [FP-CL10B104KA8VPJC_0603-MFG]  (hidden comment: CL10B104KA8VPJC)
C126  Cap_F: 100nF  [FP-CL10B104KA8VPJC_0603-MFG]  (hidden comment: CL10B104KA8VPJC)
C127  VDC_V: 100V  Cap_F: 100pF  [FP-06031C101JAT2A_0603-MFG]  (hidden comment: 06031C101JAT2A)
C128  Cap_F: 100nF  [FP-CL10B104KA8VPJC_0603-MFG]  (hidden comment: CL10B104KA8VPJC)
C129  Cap_F: 100nF  [FP-CL10B104KA8VPJC_0603-MFG]  (hidden comment: CL10B104KA8VPJC)
C130  Cap_F: 100nF  [FP-CL10B104KA8VPJC_0603-MFG]  (hidden comment: CL10B104KA8VPJC)
C131  VDC_V: 100V  Cap_F: 100pF  [FP-06031C101JAT2A_0603-MFG]  (hidden comment: 06031C101JAT2A)
C132  Cap_F: 100nF  [FP-CL10B104KA8VPJC_0603-MFG]  (hidden comment: CL10B104KA8VPJC)
C133  Cap_F: 100nF  [FP-CL10B104KA8VPJC_0603-MFG]  (hidden comment: CL10B104KA8VPJC)
C146  Cap_F: 100nF  [FP-CL10B104KA8VPJC_0603-MFG]  (hidden comment: CL10B104KA8VPJC)
D33  SBR0560S1-7  [SOD-123]
H13  NY PMS 440 0025 PH  [NY PMS 440 0025 PH]
H14  NY PMS 440 0025 PH  [NY PMS 440 0025 PH]
H15  NY PMS 440 0025 PH  [NY PMS 440 0025 PH]
J28  0022111031  [FP-0022111031_HDR3-MFG]  (value not drawn)
J29  0022111031  [FP-0022111031_HDR3-MFG]  (value not drawn)
Q2  DMN3042L-13  [FP-DMN3042L-13_SOT23-MFG]
R186  ValueDisplayed: 47  [0603]  (hidden comment: ERJ-3GEYJ470V)
R187  ValueDisplayed: 200  [0603]  (hidden comment: RT0603BRD07200RL)
R188  PackageReference: 0603  Res_ohm: 10k  [FP-CRCW060310K0JNEBC_0603-MFG]  (hidden comment: CRCW060310K0JNEBC)
R189  ValueDisplayed: 47  [0603]  (hidden comment: ERJ-3GEYJ470V)
R190  ValueDisplayed: 680  [0603]  (hidden comment: RC0603FR-07680RL)
R191  ValueDisplayed: 47  [0603]  (hidden comment: ERJ-3GEYJ470V)
R192  ValueDisplayed: 680  [0603]  (hidden comment: RC0603FR-07680RL)
R218  value 0  [FP-ERJ-H3G0R00V_0603-MFG]  (hidden comment: ERJ-H3G0R00V)
R219  value 0  [FP-ERJ-H3G0R00V_0603-MFG]  (hidden comment: ERJ-H3G0R00V)
U14  ISOTMP35BEDFQRQ1  [DFQ0007A-MFG]
U15  ISOTMP35BEDFQRQ1  [DFQ0007A-MFG]
U16  TLV9001IDBVR  [DBV0005A_N]
U17  ISOTMP35BEDFQRQ1  [DFQ0007A-MFG]
U18  TLV9001IDBVR  [DBV0005A_N]
U29  SN74LV1T34DBVR  [DBV0005A_N]  (parts A,B of 2)

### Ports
FAN_EN (in), FAN_PWM (in), NTC1_N (in), NTC1_P (in), NTC2_N (in), NTC2_P (in), TEMP_HS1 (out), TEMP_HS2 (out), TEMP_HS3 (out), TEMP_PM1 (out), TEMP_PM2 (out)

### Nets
3V3: C123.1 C126.1 C129.1 C130.1 C133.1 R218.2 R219.2 U14.1(VDD) U15.1(VDD) U16.5(V+) U17.1(VDD) U18.5(V+)
5V: C146.1 U29.5(VCC)
12V_IN: C122.1(+) D33.1(K) J28.2 J29.2
GND: C122.2(-) C123.2 C124.1 C125.2 C126.2 C127.1 C128.2 C129.2 C130.2 C131.1 C132.2 C133.2 C146.2 Q2.2(S) R188.1 R190.1 R192.1 U14.3(GND) U15.3(GND) U16.2(V-) U17.3(GND) U18.2(V-) U29.3(GND)
FAN_EN: R187.1 ; port FAN_EN
FAN_PWM: U29.2(A) ; port FAN_PWM
NTC1_N: R190.2 U16.3(IN+) ; port NTC1_N
NTC1_P: R218.1 ; port NTC1_P
NTC2_N: R192.2 U18.3(IN+) ; port NTC2_N
NTC2_P: R219.1 ; port NTC2_P
TEMP1: C124.2 R186.1 ; port TEMP_HS1
TEMP2: C127.2 R189.1 ; port TEMP_HS2
TEMP3: C131.2 R191.1 ; port TEMP_HS3
TEMP4: U16.1(OUT) U16.4(IN-) ; port TEMP_PM1
TEMP5: U18.1(OUT) U18.4(IN-) ; port TEMP_PM2
NetC125_1: C125.1 R186.2 U14.4(VOUT)
NetC128_1: C128.1 R189.2 U15.4(VOUT)
NetC132_1: C132.1 R191.2 U17.4(VOUT)
NetD33_2: D33.2(A) J28.3 J29.3 Q2.3(D)
NetH13_1: H13.1 U14.5(TSENSE) U14.6(TSENSE) U14.7(TSENSE)
NetH14_1: H14.1 U15.5(TSENSE) U15.6(TSENSE) U15.7(TSENSE)
NetH15_1: H15.1 U17.5(TSENSE) U17.6(TSENSE) U17.7(TSENSE)
NetJ28_1: J28.1 J29.1 U29.4(Y)
NetQ2_1: Q2.1(G) R187.2 R188.2

Not connected (* = marked no-connect by the designer): U14 2(NC)*; U15 2(NC)*; U17 2(NC)*; U29 1(NC)*

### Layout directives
net class HVM: 3V3, 5V, 12V_IN, GND

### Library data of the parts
C122 = CMP-0081462-1: CAP, AL, 100 µF, 25 V, +/- 20%, SMD; Manufacturer: Nichicon; TaMin_C: -55°C; Polarized: Y; SizeAreaWB_mm2: 77.4; U/M: EA; Value: 100uF; TaMax_C: 105°C; SizeZ_mm: 8; SizeX_mm: 7; SizeY_mm: 6.6; Cap_Case: 6.3x7.7mm; SizeArea_mm2: 46.2; CompType: Capacitor; AEC Qualified: N; IRMS_A: 91mA; AEC Category: Q200
C123 C125 C126 C128-C130 C132 C133 C146 = CMP-0121051-1: Automotive CAP, 100㎋, 25V, ±10%, X7R, 0603, 5mm Bending; Manufacturer: Samsung; AEC Grade: Grade 1; AEC Qualified: Yes; SizeZ_mm: 0.9mm; TempCo: 15%; Value: 100nF
C124 C127 C131 = CMP-0096605-1: 100 pF ±5% 100V Ceramic Capacitor X7R 0603 (1608 Metric); Manufacturer: KYOCERA AVX; TempCo: 15%; AEC Qualified: No; SizeZ_mm: 0.9mm; Value: 100pF
D33 = CMP-0028951-2: Diode, Schottky, 60 V, 0.5 A, SOD-123; Manufacturer: Diodes Inc.; TJmax_C: 150°C; SizeArea_mm2: 6.545; SizeZ_mm: 1.35; Value2: 0.5V; SizeAreaWB_mm2: 13.095; Value: 60V; Green_REACh: Incomplete; Value1: 0.5A; SizeX_mm: 3.85; Vf_V: 500mV; AEC Qualified: N; AEC Category: Q101; SizeY_mm: 1.7; Green_Lifecycle: Not Set; Io_A: 500mA
H13-H15 = CMP-0003617-1: as H16 on sheet TIDA-011012-MV Power Conversion
J28 J29 = CMP-0122568-1: Mini-Latch™ Wire-to-Board Header, Vertical, with Friction Ramp, 3 Circuits, Gold (Au) Plating; Manufacturer: Molex; ContactFinish: Gold,Nickel; Current_A: 3A; Row_Count: 1; Voltage_V: 250V; AEC Qualified: No; Conn Gender: Male; DUT-Pitch_mm: 2.5mm; SizeZ_mm: 12.1mm
Q2 = CMP-0089138-1: MOSFET N-CH 30V 5.8A SOT23; Manufacturer: Diodes; Reverse Recovery Charge: 1.9nC; Pulse Drain Current: 30A; Power_W: 0.72W; Turn Off Delay Time: 13.9ns; Rthja Max: 171°C/W; TJmax_C: +150°C; Typ Forward Diode Voltage: 0.7V; ChMode: False; SizeZ_mm: 1.1mm; Vgs_V: 12V; AEC Qualified: No; Input Capacitace At Vds: 570pF @ 15V; Threshold Vgs Max: 1.4V; Threshold Vgs Min: 0.6V; VdsMax_V: 1.2V; Number Of Channels: 1; Rdson45_ohm: 21m; Reverse Recovery Time: 7.8ns; QgTyp_nC: 13.3nC @ 10V; Standoff Height: 0.013mm; Turn On Delay Time: 1.5ns
R186 R189 R191 = CMP-0025880-3: RES, 47, 5%, 0.1 W, AEC-Q200 Grade 0, 0603; Manufacturer: Panasonic; Power_W: 100mW; TempCo: 200 ppm/C; Value_Code: 47R0; U/M: EA; Value: 47; EIA_Code: E24; SizeX_mm: 1.6; SizeY_mm: 0.8; SizeZ_mm: 1; Value2: 0.1W; SizeArea_mm2: 1.28; AEC Qualified: Y; AEC Grade: 0; AEC Category: Q200
R187 = CMP-0023921-2: RES, 200, 0.1%, 0.1 W, 0603; Manufacturer: Yageo America; Power_W: 100mW; TempCo: 25 ppm/C; Value_Code: 200R; U/M: EA; Value: 200; EIA_Code: E192; SizeX_mm: 1.6; SizeY_mm: 0.8; SizeZ_mm: 1; Value2: 0.1W; SizeArea_mm2: 1.28; VDC_V: 75V; AEC Category: Q200
R188 = CMP-0098286-1: 10 kOhms ±5% 0.1W, 1/10W Chip Resistor 0603 (1608 Metric) Thick Film; Manufacturer: Vishay; AEC Qualified: No; Power_W: 100mW; SizeZ_mm: 0.55mm; TempCo: 200ppm/°C; VDC_V: 75V; Value: 10k
R190 R192 = CMP-0023235-5: RES, 680, 1%, 0.1 W, 0603; Manufacturer: Yageo; Power_W: 100mW; TempCo: 100 ppm/C; Value_Code: 680R; Value: 680; SizeX_mm: 1.6; SizeY_mm: 0.8; SizeZ_mm: 1; Value2: 0.1W; SizeArea_mm2: 1.28; AEC Qualified: N; VDC_V: 75V; AEC Category: Q200; SizeAreaWB_mm2: 4.68
R218 R219 = CMP-0097467-1: 0 Ohms Jumper 0.125W, 1/8W Chip Resistor 0603 (1608 Metric) Automotive AEC-Q200 Thick Film; Manufacturer: Panasonic; VDC_V: 75V; Power_W: 125mW; AEC Qualified: Yes; SizeZ_mm: 0.55mm; AEC Grade: Grade 0
U14 U15 U17 = CMP-0122473-1: Automotive ±1.5°C, 3-kVRMS Isolated Temperature Sensor With Analog Output With < 2 Seconds Response Time and 500VRMS Working Voltage; Manufacturer: Texas Instruments; SizeZ_mm: 1.75mm; AEC Qualified: Yes; AEC Grade: Grade 0; Max Supply Voltage: 5.5V; Min Supply Voltage: 2.3V; Operating Supply Current: 10uA; Sensor Output: Analog Voltage; Standoff Height: 0.11mm; TaMax_C: +150°C; TaMin_C: -40°C; TJmax_C: +155°C
U16 U18 = CMP-0081550-1: Low-Power, Rail-to-Rail In and Out, 1-MHz Operational Amplifier, DBV0005A (SOT-23-5); Alternate PartNumber: TLV9001IDBVT; Alternate Manufacturer: Texas Instruments; SizeAreaWB_mm2: 14.82; SizeZ_mm: 1.45; SizeX_mm: 2.8; SizeY_mm: 2.9; SizeArea_mm2: 8.12; CompType: IC; AEC Qualified: N; AEC Category: Q200
U29 = CMP-0051712-2: Single Power Supply BUFFER Logic Level Shifter (no enable), DBV0005A, LARGE T&R; Manufacturer: Texas Instruments; F @ Nom Voltage(Max)(Mhz): 50; Logic: True; ICC @ Nom Voltage(Max)(mA): 0.01; Output Drive (IOL/IOH)(Max)(mA): 8/-8; Special Features: 1.8V to 3.3V Up Translation,3.3V to 1.8V Down Translation,5V Input Tolerant; VCC(Max)(V): 5.5; Technology Family: LV1T; tpd @ Nom Voltage(Max)(ns): 14.5,9.5,8.0,6.5; Rating: Catalog; Sub-Family: Non-Inverting Buffer/Driver; Input Type: TTL; VCC(Min)(V): 1.6; 3-State Output: Yes; Bits(#): 1; Voltage(Nom)(V): 1.8,2.5,3.3,5.5; Output Type: CMOS; AEC Category: Q200; AEC Qualified: N; CompType: IC; SizeAreaWB_mm2: 14.82; SizeArea_mm2: 8.12; SizeX_mm: 2.8; SizeY_mm: 2.9; SizeZ_mm: 1.45

## Sheet TIDA-011012-MV Optical Interface.SchDoc
size 431 x 279 mm; Date: Not shown in title block; ApprovedBy: Not shown in title block; CheckedBy: Not shown in title block; Author: Not shown in title block; CompanyName: Not shown in title block; Engineer: Not shown in title block; Organization: Not shown in title block; Address1: Not shown in title block; Address2: Not shown in title block; Address3: Not shown in title block; Address4: Not shown in title block; DocumentNumber: 10; Revision: Use project parameter SCH_Rev; SheetNumber: 10; SheetTotal: 11; PageSetup: Record=PageOptions¦CenterHorizontal=True¦CenterVertical=True¦PrintScale=1.00¦XCorrection=1.00¦YCorrection=1.00¦PrintKind=0¦BorderSize=5000000¦LeftOffset=0¦BottomOffset=0¦Orientation=2¦PaperLength=1000¦PaperWidth=1000¦Scale=100¦PaperSource=15¦PrintQuality=600¦MediaType=1¦DitherType=10¦PaperKind=Letter¦PrintScaleMode=1
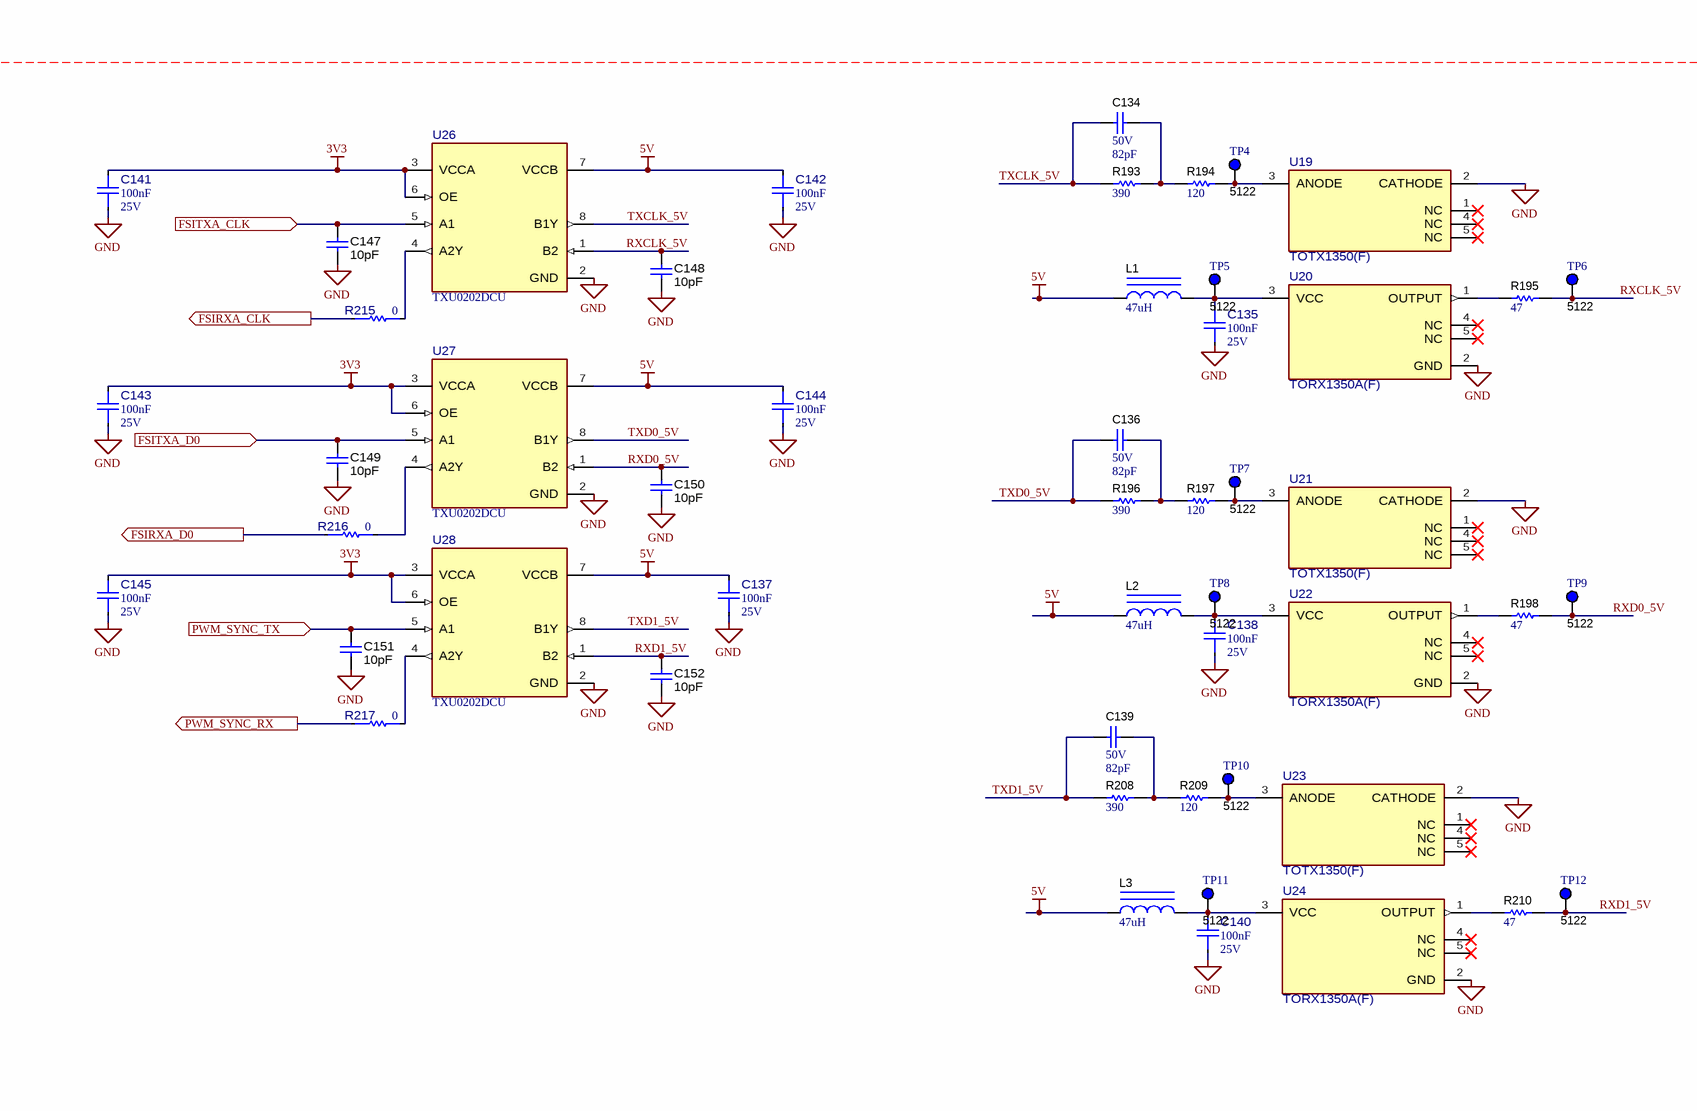
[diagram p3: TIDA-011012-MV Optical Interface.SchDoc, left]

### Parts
C134  VDC_V: 50V  ValueDisplayed: 82pF  [0603]  (hidden comment: C0603C820K5GACTU)
C135  Cap_F: 100nF  VDC_V: 25V  [FP-GMC10X7R104K25NT_0603-MFG]  (hidden comment: GMC10X7R104K25NT)
C136  VDC_V: 50V  ValueDisplayed: 82pF  [0603]  (hidden comment: C0603C820K5GACTU)
C137  Cap_F: 100nF  VDC_V: 25V  [FP-GMC10X7R104K25NT_0603-MFG]  (hidden comment: GMC10X7R104K25NT)
C138  Cap_F: 100nF  VDC_V: 25V  [FP-GMC10X7R104K25NT_0603-MFG]  (hidden comment: GMC10X7R104K25NT)
C139  VDC_V: 50V  ValueDisplayed: 82pF  [0603]  (hidden comment: C0603C820K5GACTU)
C140  Cap_F: 100nF  VDC_V: 25V  [FP-GMC10X7R104K25NT_0603-MFG]  (hidden comment: GMC10X7R104K25NT)
C141  Cap_F: 100nF  VDC_V: 25V  [FP-GMC10X7R104K25NT_0603-MFG]  (hidden comment: GMC10X7R104K25NT)
C142  Cap_F: 100nF  VDC_V: 25V  [FP-GMC10X7R104K25NT_0603-MFG]  (hidden comment: GMC10X7R104K25NT)
C143  Cap_F: 100nF  VDC_V: 25V  [FP-GMC10X7R104K25NT_0603-MFG]  (hidden comment: GMC10X7R104K25NT)
C144  Cap_F: 100nF  VDC_V: 25V  [FP-GMC10X7R104K25NT_0603-MFG]  (hidden comment: GMC10X7R104K25NT)
C145  Cap_F: 100nF  VDC_V: 25V  [FP-GMC10X7R104K25NT_0603-MFG]  (hidden comment: GMC10X7R104K25NT)
C147  Cap_F: 10pF  [0603]  (hidden comment: 0603ZC100KAT2A)
C148  Cap_F: 10pF  [0603]  (hidden comment: 0603ZC100KAT2A)
C149  Cap_F: 10pF  [0603]  (hidden comment: 0603ZC100KAT2A)
C150  Cap_F: 10pF  [0603]  (hidden comment: 0603ZC100KAT2A)
C151  Cap_F: 10pF  [0603]  (hidden comment: 0603ZC100KAT2A)
C152  Cap_F: 10pF  [0603]  (hidden comment: 0603ZC100KAT2A)
L1  ValueDisplayed: 47uH  [NLCV25]  (hidden comment: NLFV25T-470K-PF)
L2  ValueDisplayed: 47uH  [NLCV25]  (hidden comment: NLFV25T-470K-PF)
L3  ValueDisplayed: 47uH  [NLCV25]  (hidden comment: NLFV25T-470K-PF)
R193  ValueDisplayed: 390  [0603]  (hidden comment: RC0603FR-07390RL)
R194  ValueDisplayed: 120  [0603]  (hidden comment: RC0603FR-07120RL)
R195  ValueDisplayed: 47  [0603]  (hidden comment: CRCW060347R0JNEA)
R196  ValueDisplayed: 390  [0603]  (hidden comment: RC0603FR-07390RL)
R197  ValueDisplayed: 120  [0603]  (hidden comment: RC0603FR-07120RL)
R198  ValueDisplayed: 47  [0603]  (hidden comment: CRCW060347R0JNEA)
R208  ValueDisplayed: 390  [0603]  (hidden comment: RC0603FR-07390RL)
R209  ValueDisplayed: 120  [0603]  (hidden comment: RC0603FR-07120RL)
R210  ValueDisplayed: 47  [0603]  (hidden comment: CRCW060347R0JNEA)
R215  value 0  [FP-ERJ-H3G0R00V_0603-MFG]  (hidden comment: ERJ-H3G0R00V)
R216  value 0  [FP-ERJ-H3G0R00V_0603-MFG]  (hidden comment: ERJ-H3G0R00V)
R217  value 0  [FP-ERJ-H3G0R00V_0603-MFG]  (hidden comment: ERJ-H3G0R00V)
TP4  5122  [Keystone5122]
TP5  5122  [Keystone5122]
TP6  5122  [Keystone5122]
TP7  5122  [Keystone5122]
TP8  5122  [Keystone5122]
TP9  5122  [Keystone5122]
TP10  5122  [Keystone5122]
TP11  5122  [Keystone5122]
TP12  5122  [Keystone5122]
U19  TOTX1350(F)  [FP-TOTX1350(F)_REC_OPT_PTH-MFG]
U20  TORX1350A(F)  [FP-TORX1350A(F)_OPTIC_RECIEVER_13MM0_13MM5-MFG]
U21  TOTX1350(F)  [FP-TOTX1350(F)_REC_OPT_PTH-MFG]
U22  TORX1350A(F)  [FP-TORX1350A(F)_OPTIC_RECIEVER_13MM0_13MM5-MFG]
U23  TOTX1350(F)  [FP-TOTX1350(F)_REC_OPT_PTH-MFG]
U24  TORX1350A(F)  [FP-TORX1350A(F)_OPTIC_RECIEVER_13MM0_13MM5-MFG]
U26  TXU0202DCU  [DCU0008A-MFG]
U27  TXU0202DCU  [DCU0008A-MFG]
U28  TXU0202DCU  [DCU0008A-MFG]

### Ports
FSIRXA_CLK (out), FSIRXA_D0 (out), FSITXA_CLK (in), FSITXA_D0 (in), PWM_SYNC_RX (out), PWM_SYNC_TX (in)

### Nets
3V3: C141.2 C143.2 C145.2 U26.3(VCCA) U26.6(OE) U27.3(VCCA) U27.6(OE) U28.3(VCCA) U28.6(OE)
5V: C137.2 C142.2 C144.2 L1.1 L2.1 L3.1 U26.7(VCCB) U27.7(VCCB) U28.7(VCCB)
GND: C135.1 C137.1 C138.1 C140.1 C141.1 C142.1 C143.1 C144.1 C145.1 C147.2 C148.2 C149.2 C150.2 C151.2 C152.2 U19.2(CATHODE) U20.2(GND) U21.2(CATHODE) U22.2(GND) U23.2(CATHODE) U24.2(GND) U26.2(GND) U27.2(GND) U28.2(GND)
FSIRXA_CLK: R215.1 ; port FSIRXA_CLK
FSIRXA_D0: R216.1 ; port FSIRXA_D0
FSITXA_CLK: C147.1 U26.5(A1) ; port FSITXA_CLK
FSITXA_D0: C149.1 U27.5(A1) ; port FSITXA_D0
PWM_SYNC_RX: R217.1 ; port PWM_SYNC_RX
PWM_SYNC_TX: C151.1 U28.5(A1) ; port PWM_SYNC_TX
RXCLK_5V: C148.1 R195.2 TP6.1 U26.1(B2)
RXD0_5V: C150.1 R198.2 TP9.1 U27.1(B2)
RXD1_5V: C152.1 R210.2 TP12.1 U28.1(B2)
TXCLK_5V: C134.2 R193.1 U26.8(B1Y)
TXD0_5V: C136.2 R196.1 U27.8(B1Y)
TXD1_5V: C139.2 R208.1 U28.8(B1Y)
NetC134_1: C134.1 R193.2 R194.1
NetC135_2: C135.2 L1.2 TP5.1 U20.3(VCC)
NetC136_1: C136.1 R196.2 R197.1
NetC138_2: C138.2 L2.2 TP8.1 U22.3(VCC)
NetC139_1: C139.1 R208.2 R209.1
NetC140_2: C140.2 L3.2 TP11.1 U24.3(VCC)
NetR194_2: R194.2 TP4.1 U19.3(ANODE)
NetR195_1: R195.1 U20.1(OUTPUT)
NetR197_2: R197.2 TP7.1 U21.3(ANODE)
NetR198_1: R198.1 U22.1(OUTPUT)
NetR209_2: R209.2 TP10.1 U23.3(ANODE)
NetR210_1: R210.1 U24.1(OUTPUT)
NetR215_2: R215.2 U26.4(A2Y)
NetR216_2: R216.2 U27.4(A2Y)
NetR217_2: R217.2 U28.4(A2Y)

Not connected (* = marked no-connect by the designer): U19 1(NC)* 4(NC)* 5(NC)*; U20 4(NC)* 5(NC)*; U21 1(NC)* 4(NC)* 5(NC)*; U22 4(NC)* 5(NC)*; U23 1(NC)* 4(NC)* 5(NC)*; U24 4(NC)* 5(NC)*

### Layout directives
net class HVM: 3V3, 5V, GND, RXCLK_5V, RXD0_5V, RXD1_5V, TXCLK_5V, TXD0_5V, TXD1_5V

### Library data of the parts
C134 C136 C139 = CMP-0006970-4: CAP, CERM, 82 pF, 50 V, +/- 10%, C0G/NP0, 0603; Manufacturer: Kemet; TaMin_C: -55°C; Polarized: N; SizeAreaWB_mm2: 4.68; Value1: Unknown; U/M: EA; Value: 82pF; TaMax_C: 125°C; SizeZ_mm: 1; SizeX_mm: 1.6; SizeY_mm: 0.8; SizeArea_mm2: 1.28; AEC Category: Q200
C135 C137 C138 C140-C145 = CMP-0094950-1: 0.1 µF ±10% 25V Ceramic Capacitor X7R 0603 (1608 Metric); Manufacturer: CAL-CHIP ELECTRONICS; AEC Qualified: No; SizeZ_mm: 1mm; Value: 100nF; ValueDisplayed: 0.1uF; TempCo: 30ppm/°C
C147-C152 = CMP-0006811-4: CAP, CERM, 10 pF, 10 V, +/- 10%, X7R, 0603; Manufacturer: AVX; TaMin_C: -55°C; Polarized: N; SizeAreaWB_mm2: 4.68; Value1: Unknown; U/M: EA; Value: 10pF; TaMax_C: 125°C; SizeZ_mm: 1; SizeX_mm: 1.6; SizeY_mm: 0.8; Value2: 10V; SizeArea_mm2: 1.28; AEC Category: Q200
L1-L3 = CMP-0062508-2: Inductor, Shielded, Ferrite, 47 uH, 0.06 A, 1.7 ohm, SMD; Manufacturer: TDK; Isat: 0.06A @ 10% inductance drop; Irms: 0.06A @ 20C rise; Green_Lifecycle: Active; SizeAreaWB_mm2: 9.8; DCR_ohm: 1.7; Green_REACh: Passed; Value1: 1.7 ohm; Value: 47uH; Imax_A: 60mA; SizeZ_mm: 2; SizeX_mm: 2.5; SizeY_mm: 1.8; Value2: 0.06A; SizeArea_mm2: 4.5; Ind_H: 47µH; AEC Category: Q200
R193 R196 R208 = CMP-0023069-5: RES, 390, 1%, 0.1 W, 0603; Manufacturer: Yageo; Power_W: 100mW; TempCo: 100 ppm/C; Value_Code: 390R; Value: 390; SizeX_mm: 1.6; SizeY_mm: 0.8; SizeZ_mm: 1; Value2: 0.1W; SizeArea_mm2: 1.28; AEC Qualified: N; VDC_V: 75V; AEC Category: Q200; SizeAreaWB_mm2: 4.68
R194 R197 R209 = CMP-0022769-5: RES, 120, 1%, 0.1 W, 0603; Manufacturer: Yageo; Power_W: 100mW; TempCo: 100 ppm/C; Value_Code: 120R; Value: 120; SizeX_mm: 1.6; SizeY_mm: 0.8; SizeZ_mm: 1; Value2: 0.1W; SizeArea_mm2: 1.28; AEC Qualified: N; VDC_V: 75V; AEC Category: Q200; SizeAreaWB_mm2: 4.68
R195 R198 R210 = CMP-0025815-4: RES, 47, 5%, 0.1 W, AEC-Q200 Grade 0, 0603; Manufacturer: Vishay-Dale; Power_W: 100mW; TempCo: 200 ppm/C; Value_Code: 47R0; Value: 47; EIA_Code: E24; SizeX_mm: 1.6; SizeY_mm: 0.8; SizeZ_mm: 1; Value2: 0.1W; SizeArea_mm2: 1.28; AEC Qualified: Y; VDC_V: 75V; AEC Category: Q200; AEC Grade: 0
R215-R217 = CMP-0097467-1: as R218 on sheet TIDA-011012-MV Fans and Temp Sense
TP4-TP12 = CMP-0055155-2: as TP15 on sheet TIDA-011012-MV Power Conversion
U19 U21 U23 = CMP-0092228-1: Fiber Optic Transmitter 650nm 1.8V TOSLINK; Manufacturer: Toshiba; SizeZ_mm: 8.8mm; Vr_V: 5V; Min Supply Voltage: 4.75V; AEC Qualified: No; Max Supply Voltage: 5.25V; Vf_V: 2V; Standoff Height: 0.1mm; Forward Current: 6mA
U20 U22 U24 = CMP-0092227-1: Fiber Optic Receiver General Purpose 10Mbps -27dBm 4.75V ~ 5.25V; Manufacturer: Toshiba; Sensing Distance: 0.2-100m; SizeZ_mm: 8.8mm; Standoff Height: 0.1mm; AEC Qualified: No
U26-U28 = CMP-0093827-1: Single-Bit Fixed Direction Voltage-Level Translator with Schmitt-Trigger Inputs and 3-State Outputs; Manufacturer: Texas Instruments; SizeZ_mm: 0.9mm; Standoff Height: 0mm; V A Max: 5.5V; Number Of Inputs: 1; V B Min: 1.1V; PositionCount: 2; Logic Function Desc: Non-Inverting; AEC Qualified: No; Data Rate: 200Mbits/s; Propagation Delay: 8ns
